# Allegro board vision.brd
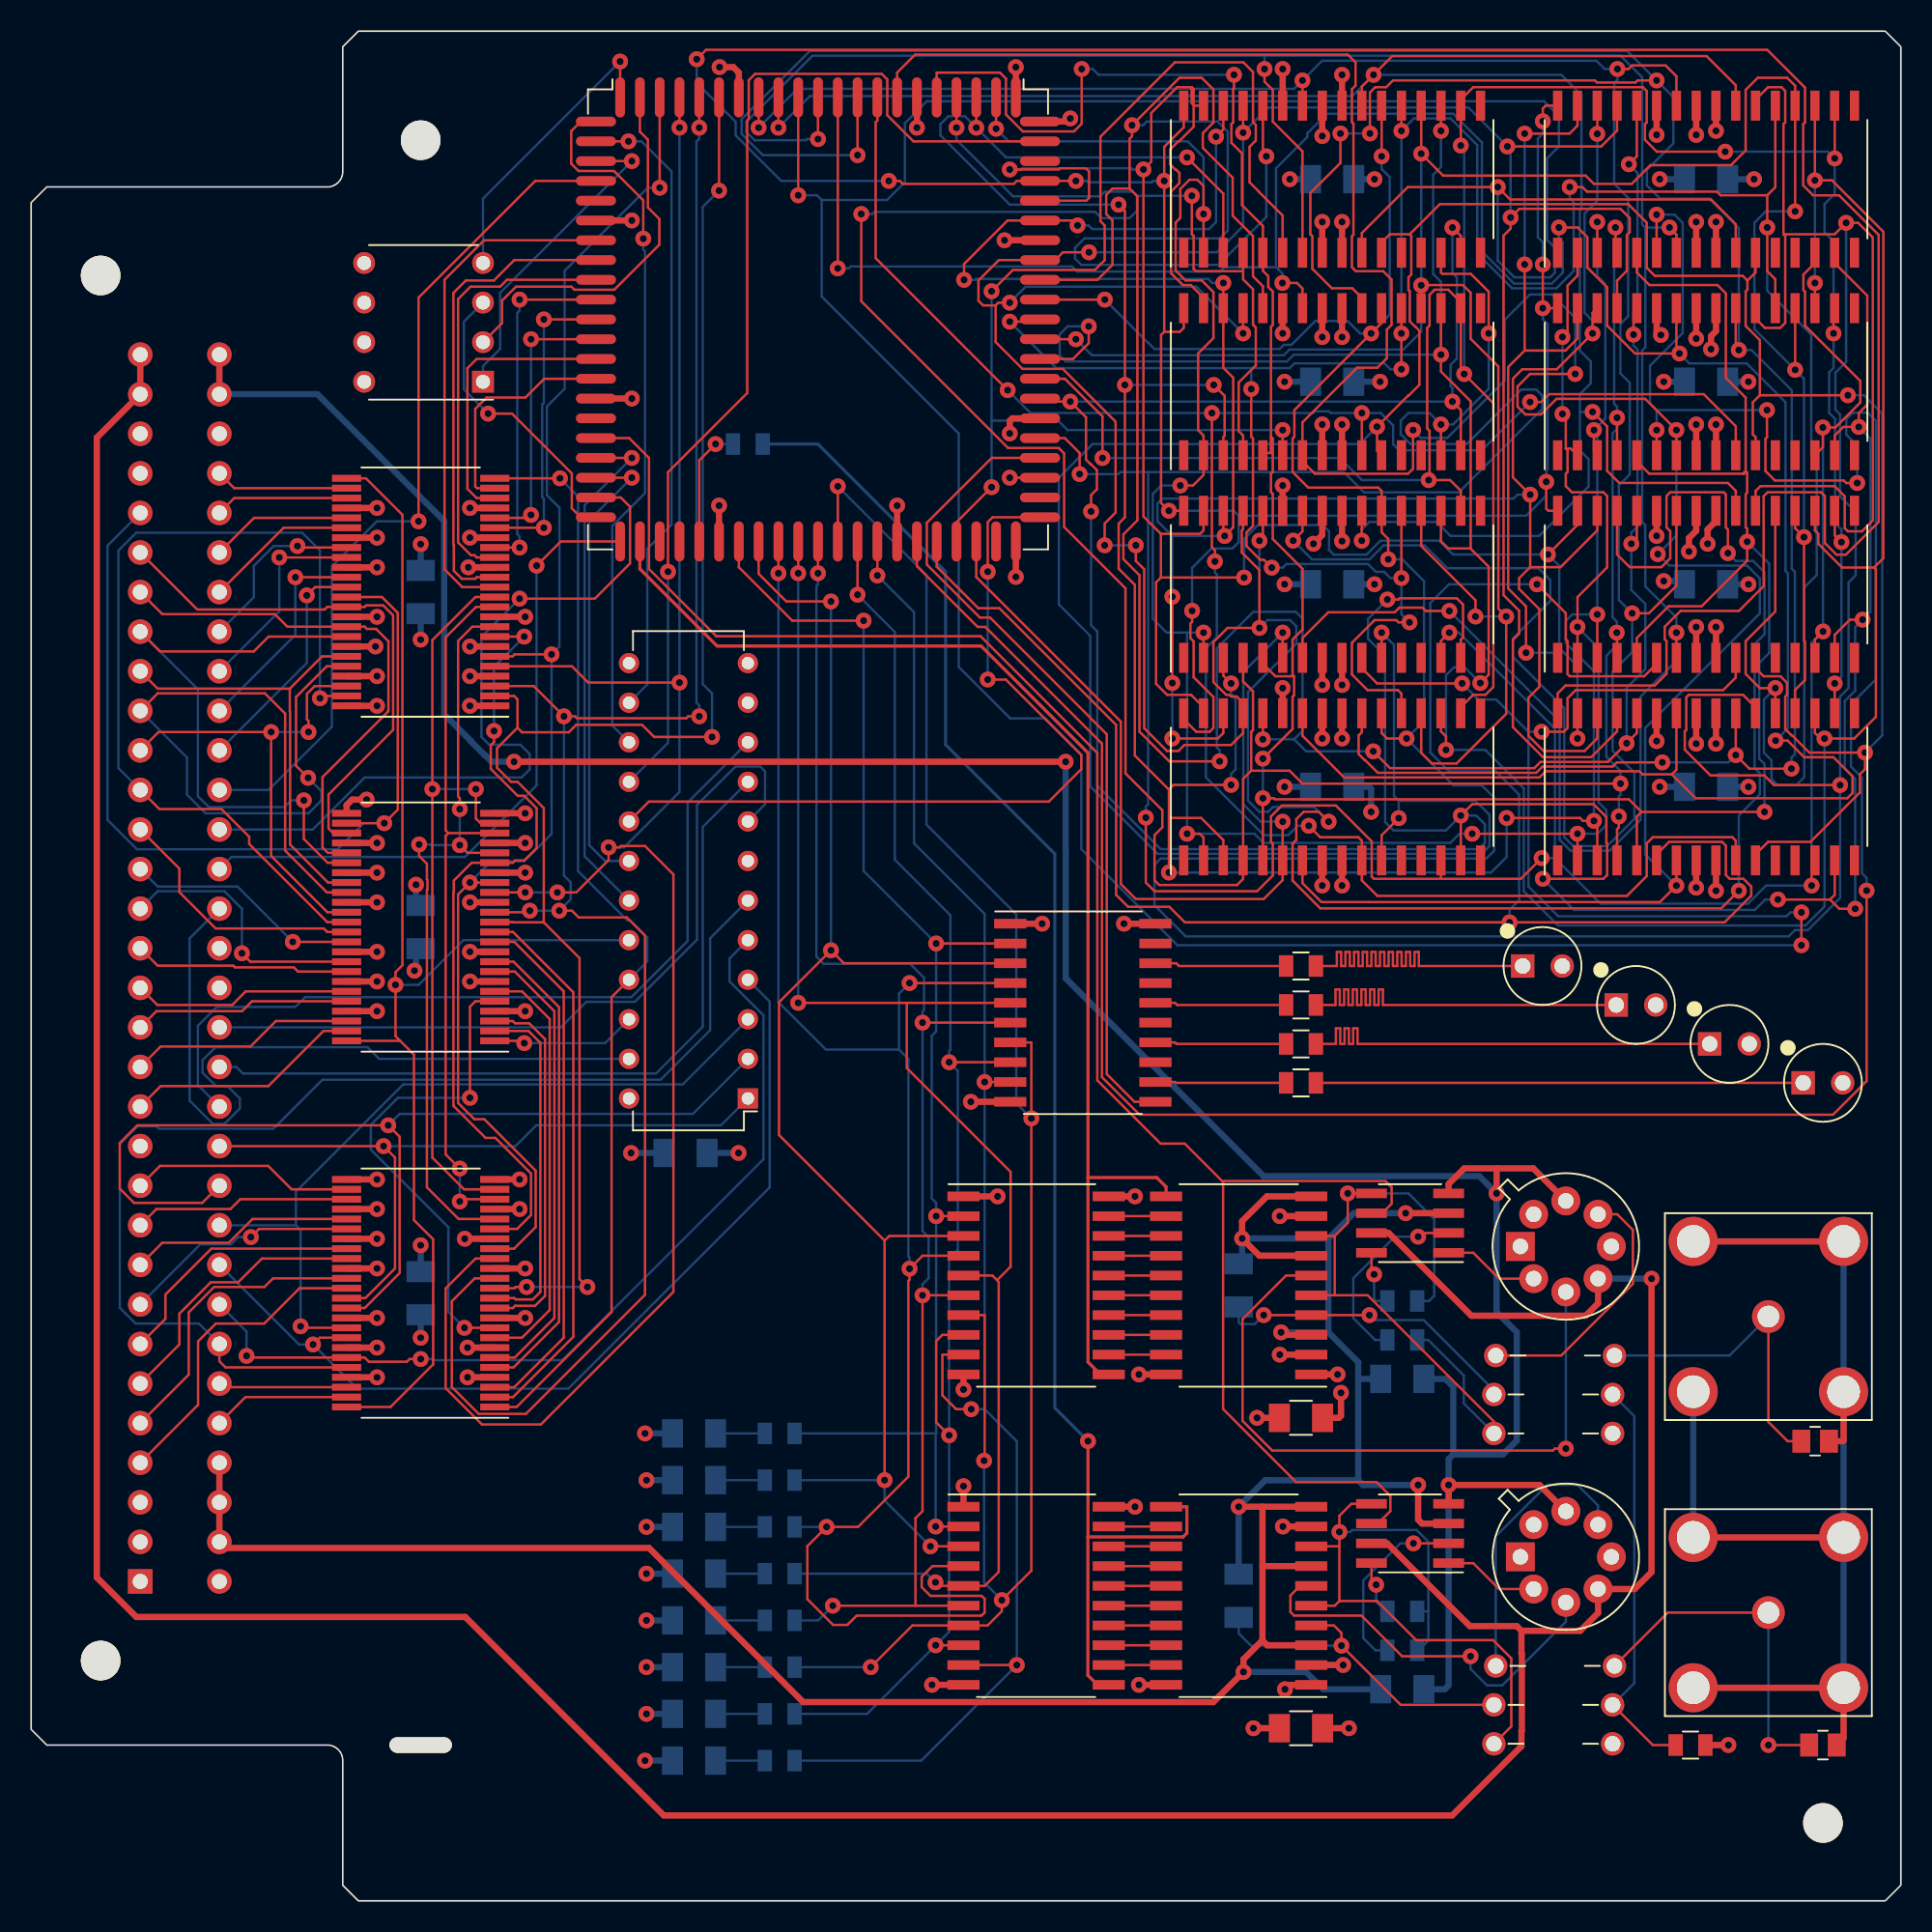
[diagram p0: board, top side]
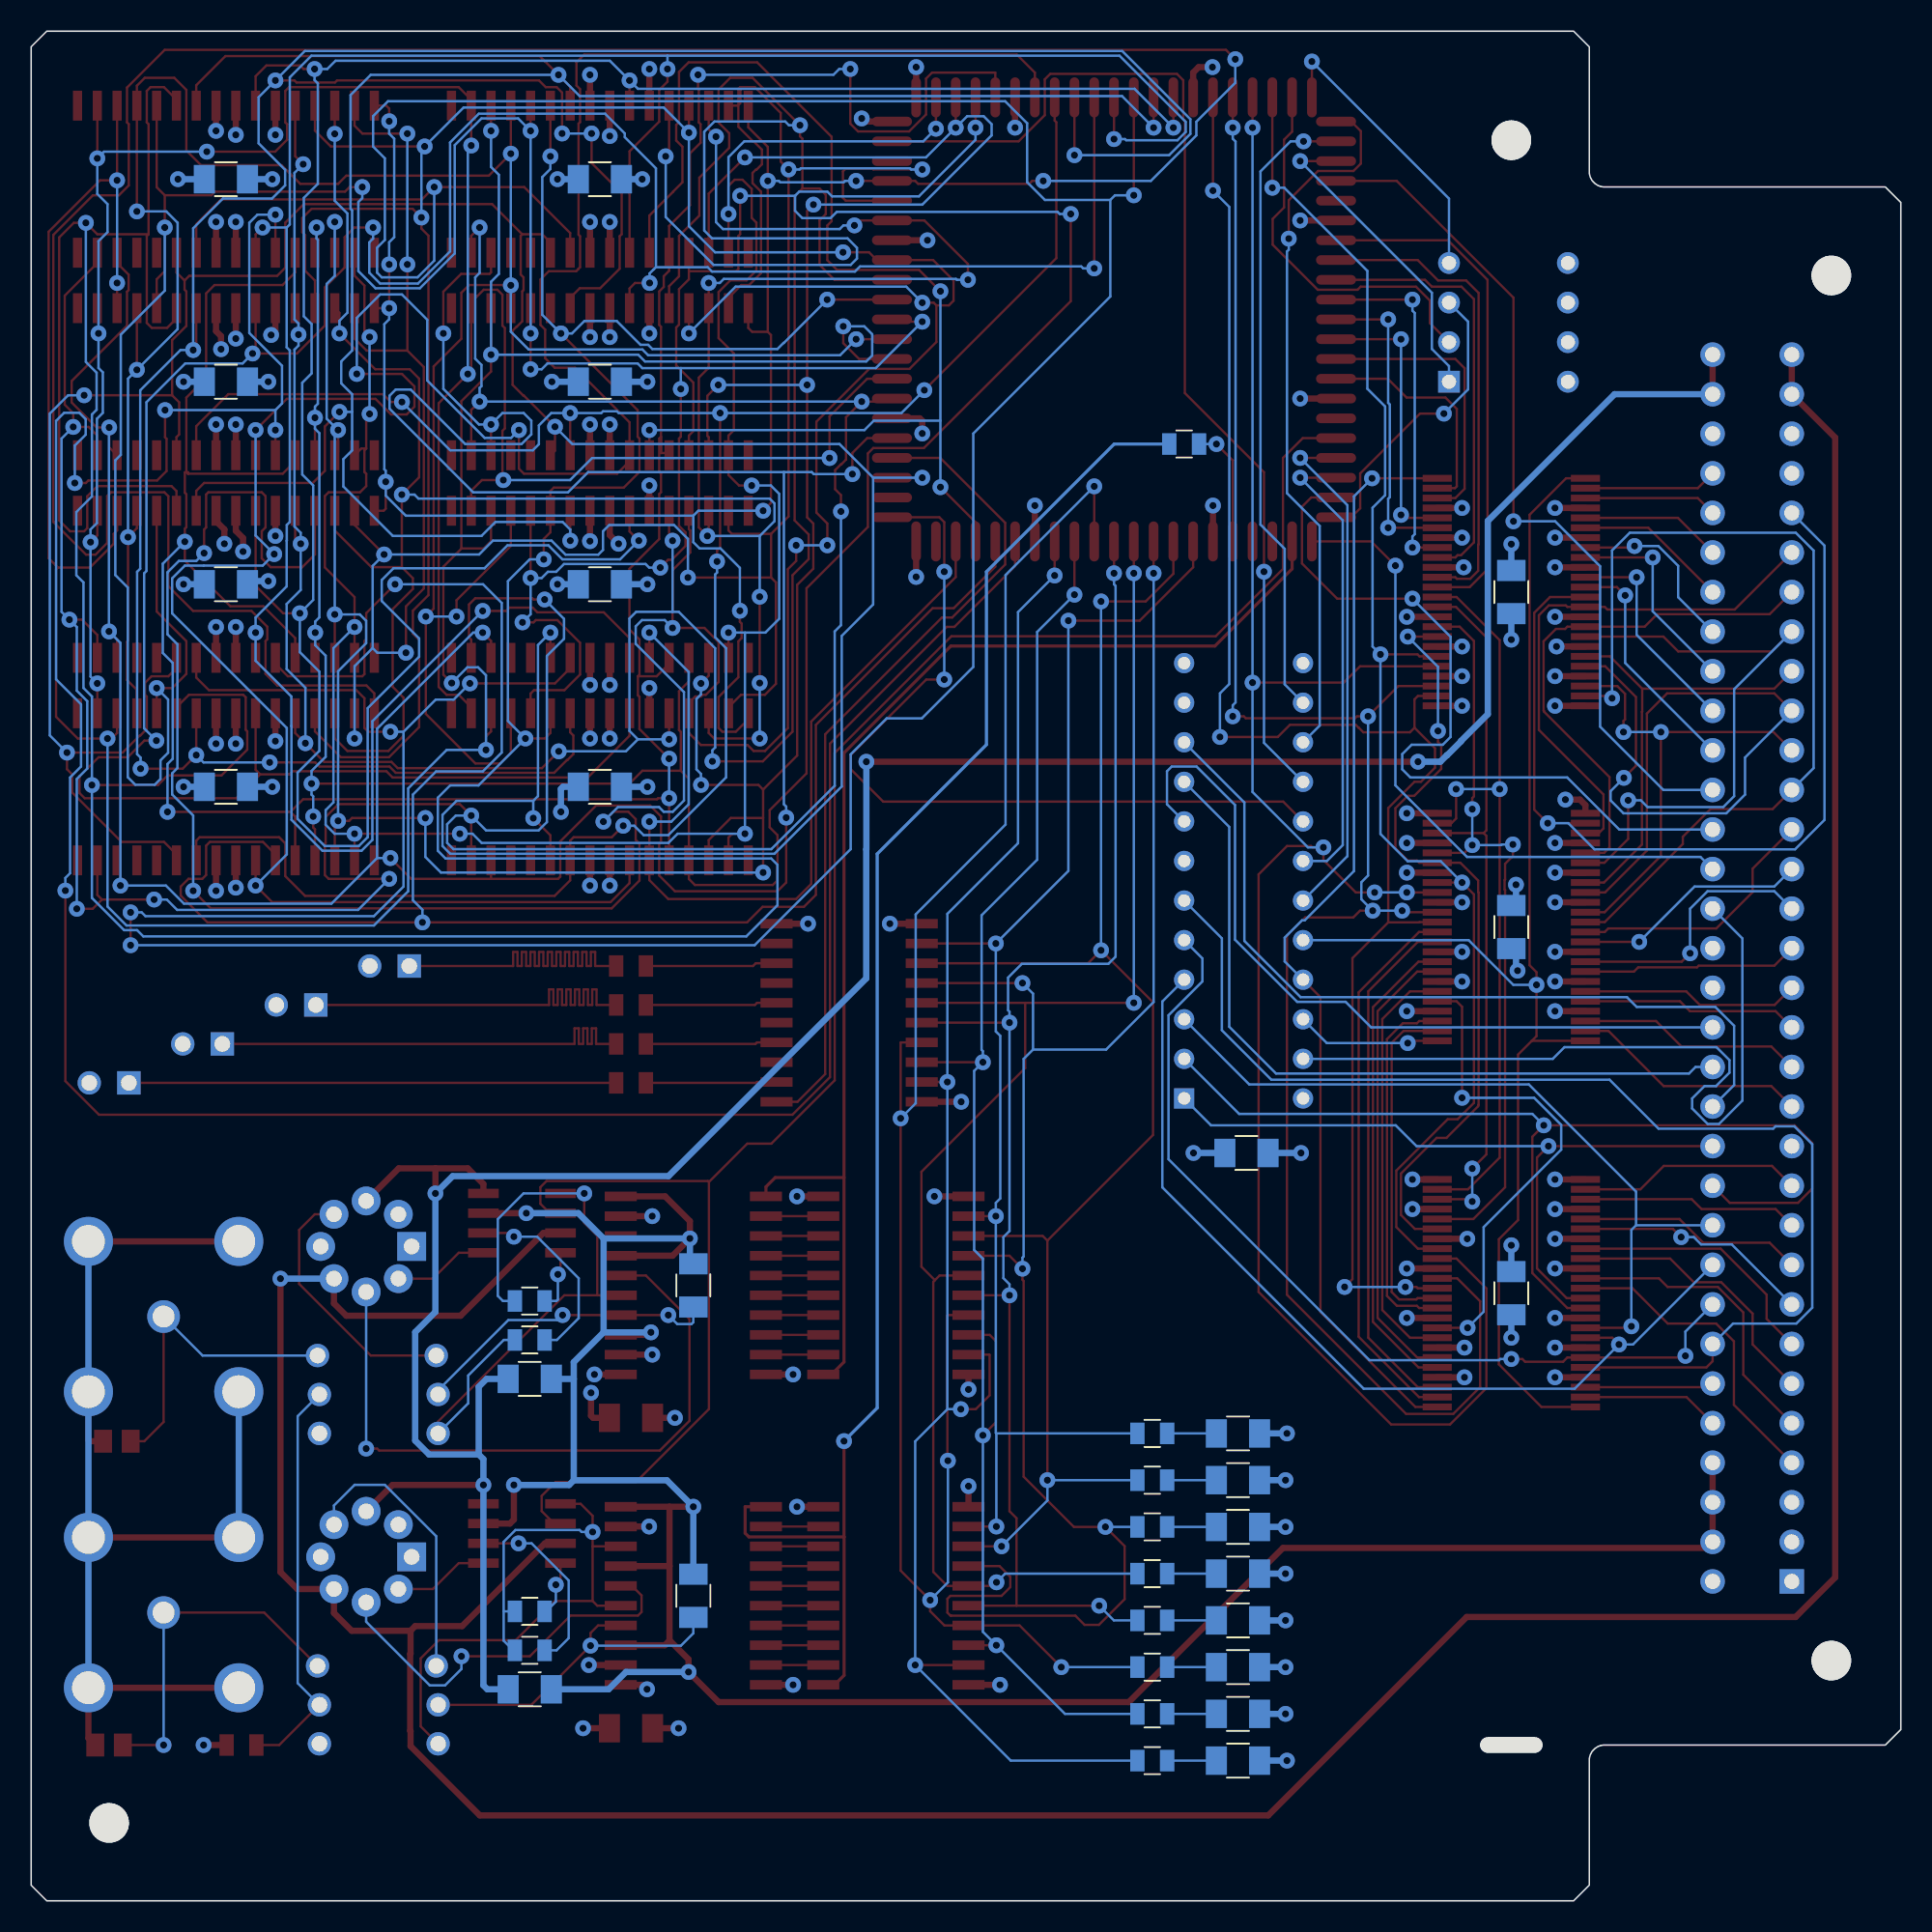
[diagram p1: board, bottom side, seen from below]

Outline 120 x 120 mm; copper layers: TOP, GND1, VCC1, VCC2, GND2, BOTTOM. Coordinates in mm from the lower left corner of the outline.

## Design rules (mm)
constraint set DEFAULT: min track width 0.15, pair gap 0.15
net group SYNC: nets VCLKA VCLKC
net group LEDNETS: nets LED1 LED2 LED3 LED4
net group MEMORY[0..28]: nets MEMORY.RA0 MEMORY.RA1 MEMORY.RA2 MEMORY.RA3 MEMORY.RA4 MEMORY.RA5 MEMORY.RA6 MEMORY.RA7 MEMORY.RA8 MEMORY.RA9 MEMORY.RA10 MEMORY.RA11 MEMORY.RA12 MEMORY.RA13 MEMORY.RA14 MEMORY.RA15 MEMORY.RCS0 MEMORY.RCS1 MEMORY.RCS2 MEMORY.RCS3 MEMORY.RD0 MEMORY.RD1 MEMORY.RD2 MEMORY.RD3 MEMORY.RD4 MEMORY.RD5 MEMORY.RD6 MEMORY.RD7 MEMORY.RWE
net group POWER: nets AGND GND_EARTH V12N V+12
net group VDNETS: nets VD0 VD1 VD2 VD3 VD4 VD5 VD6 VD7
nets with their own width: min track width 0.4; nets GND VCC

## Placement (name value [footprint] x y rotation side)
C1  0.1uF  [CAPC3216X110N]  25 39 90 bottom
C2  0.1uF  [CAPC3216X110N]  42 48 0 bottom
C3  0.1uF  [CAPC3216X110N]  25 62.5 90 bottom
C4  0.1uF  [CAPC3216X110N]  25 84 90 bottom
C5  47PF  [CAPC2012X110N]  114.5 29.5 0 top
C6  47PF  [CAPC2012X110N]  115 10 0 top
C7  0.01u  [CAPC3216X110N]  81.5 31 0 top
C8  0.01u  [CAPC3216X110N]  77.5 39.5 90 bottom
C9  0.1u  [CAPC3216X110N]  88 33.5 180 bottom
C10  0.01u  [CAPC3216X110N]  81.5 11.08 0 top
C11  0.01u  [CAPC3216X110N]  77.5 19.58 90 bottom
C12  0.1u  [CAPC3216X110N]  88 13.58 180 bottom
C13  330p  [CAPC3216X110N]  42.55 12 180 bottom
C14  330p  [CAPC3216X110N]  42.55 18 180 bottom
C15  330p  [CAPC3216X110N]  42.55 24 180 bottom
C16  330p  [CAPC3216X110N]  42.55 30 180 bottom
C17  330p  [CAPC3216X110N]  42.55 9 180 bottom
C18  330p  [CAPC3216X110N]  42.55 15 180 bottom
C19  330p  [CAPC3216X110N]  42.55 21 180 bottom
C20  330p  [CAPC3216X110N]  42.55 27 180 bottom
C21  0.1uF  [CAPC3216X110N]  83.5 71.5 0 bottom
C22  0.1uF  [CAPC3216X110N]  107.5 71.5 0 bottom
C23  0.1uF  [CAPC3216X110N]  83.5 84.5 0 bottom
C24  0.1uF  [CAPC3216X110N]  107.5 84.5 0 bottom
C25  0.1uF  [CAPC3216X110N]  83.5 97.5 0 bottom
C26  0.1uF  [CAPC3216X110N]  107.5 97.5 0 bottom
C27  0.1uF  [CAPC3216X110N]  107.5 110.5 0 bottom
C28  0.1uF  [CAPC3216X110N]  83.5 110.5 0 bottom
D1  LED  [LEDRD254W00D500H860P]  97 60 0 top
D2  LED  [LEDRD254W00D500H860P]  103 57.5 0 top
D3  LED  [LEDRD254W00D500H860P]  109 55 0 top
D4  LED  [LEDRD254W00D500H860P]  115 52.5 0 top
J1  CON64  [DIN64]  7 20.5 0 top
J2  BNC  [CONNEX_112659]  111.5 37.5 0 top
J3  BNC  [CONNEX_112659]  111.5 18.5 0 top
L1  47u  [INDAD762W79L381D254P]  94 35 0 top
L2  47u  [INDAD762W79L381D254P]  94 15.08 0 top
L3  47u  [INDAD762W79L381D254P]  101.5 32.5 180 top
L4  47u  [INDAD762W79L381D254P]  101.5 30 180 top
L5  47u  [INDAD762W79L381D254P]  101.5 12.58 180 top
L6  47u  [INDAD762W79L381D254P]  101.5 10.08 180 top
NOREF  -  []  20 6.38 0 top
NOREF#2  -  []  0 20.43 0 top
NOREF#3  -  []  -74.06 -89.06 0 top
NOREF#4  -  []  25 10 90 top
NOREF#5  -  []  115 5 90 top
NOREF#6  -  []  25 10 0 top
NOREF#7  -  [unnamed#2]  25 10 0 top
NOREF#8  -  []  25 10 90 top
NOREF#9  -  []  19.78 110.37 0 top
NOREF#10  -  []  25 10 0 top
NOREF#11  -  []  119.52 119.48 0 top
NOREF#12  -  []  25 10 90 top
NOREF#13  -  []  23 0 90 top
NOREF#14  -  []  192.64 154.78 0 top
R1  150  [RESC2012X60N]  81.5 60 0 top
R2  150  [RESC2012X60N]  81.5 57.5 0 top
R3  150  [RESC2012X60N]  81.5 55 0 top
R4  150  [RESC2012X60N]  81.5 52.5 0 top
R5  2K  [RESC2012X60N]  46 93.5 0 bottom
R6  100  [RESC2012X60N]  88 38.5 180 bottom
R7  100  [RESC2012X60N]  88 36 180 bottom
R8  100  [RESC2012X60N]  88 18.58 180 bottom
R9  100  [RESC2012X60N]  88 16.08 180 bottom
R10  10K  [RESC2012X60N]  48.05 12 0 bottom
R11  10K  [RESC2012X60N]  48.05 18 0 bottom
R12  10K  [RESC2012X60N]  48.05 24 0 bottom
R13  10K  [RESC2012X60N]  48.05 30 0 bottom
R14  10K  [RESC2012X60N]  48.05 9 0 bottom
R15  10K  [RESC2012X60N]  48.05 15 0 bottom
R16  10K  [RESC2012X60N]  48.05 21 0 bottom
R17  10K  [RESC2012X60N]  48.05 27 0 bottom
R18  10K  [RESC2012X60N]  106.5 10 0 top
U1  FCT16245  [SOP63P1035X279-48N]  25 39 90 top
U2  20L10  [DIP763W46P254L3204H508Q24P]  46 51.5 90 top
U3  FCT16245  [SOP63P1035X279-48N]  25 62.5 90 top
U4  FCT16245  [SOP63P1035X279-48N]  25 84 90 top
U5  EPF8282A_LCC  [PLCC127P3022X3022X457-84N]  50.5 101.5 270 top
U6  74ACT574  [SOIC127P1034X264-20N]  67.5 57 270 top
U7  EPC1064  [DIP763W46P254L991H419Q8P]  29 97.5 90 top
U8  TLC5602A  [SOIC127P1034X264-20N]  77.5 39.5 90 top
U9  TLE2037A  [TO292P469H584-8P]  98.5 42 0 top
U10  DG419AK  [SOIC127P600X175-8N]  88.5 43.5 90 top
U11  TLC5602A  [SOIC127P1034X264-20N]  77.5 19.58 90 top
U12  TLE2037A  [TO292P469H584-8P]  98.5 22.08 0 top
U13  DG419AK  [SOIC127P600X175-8N]  88.5 23.58 90 top
U14  74ACT574  [SOIC127P1034X264-20N]  64.5 39.5 270 top
U15  74ACT574  [SOIC127P1034X264-20N]  64.5 19.58 270 top
U16  TC55B4257  [SOIC127P1032X265-32N]  83.5 71.5 0 top
U17  TC55B4257  [SOIC127P1032X265-32N]  83.5 84.5 0 top
U18  TC55B4257  [SOIC127P1032X265-32N]  83.5 97.5 0 top
U19  TC55B4257  [SOIC127P1032X265-32N]  83.5 110.5 0 top
U20  TC55B4257  [SOIC127P1032X265-32N]  107.5 71.5 0 top
U21  TC55B4257  [SOIC127P1032X265-32N]  107.5 84.5 0 top
U22  TC55B4257  [SOIC127P1032X265-32N]  107.5 97.5 0 top
U23  TC55B4257  [SOIC127P1032X265-32N]  107.5 110.5 0 top

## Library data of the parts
C1-C4 C13-C20 = CAP NP
C5 C7-C9 = CAP NP: room: CHAN1
C6 C10-C12 = CAP NP: room: CHAN2
C21-C28 = CAP NP: room: MEM
D1-D4 = PHOTODIODE_0
J1 = CON64
J2 = BNC: room: CHAN1
J3 = BNC: room: CHAN2
L1 L3 L4 = INDUCTOR: room: CHAN1
L2 L5 L6 = INDUCTOR: room: CHAN2
R1-R4 = R: room: LED
R5 R10-R17 = R
R6 R7 = R: room: CHAN1
R8 R9 R18 = R: room: CHAN2
U1 U3 U4 = FCT16245
U2 = 20L10: alternate symbols: (T:SOIC24;B:SOIC24_PE)
U5 = EPF8282A/LCC
U6 = 74ACT574: room: LED
U7 = EPC1064
U8 = TLC5602A: room: CHAN1
U9 = TLE2037A: room: CHAN1
U10 = DG419AK: room: CHAN1
U11 = TLC5602A: room: CHAN2
U12 = TLE2037A: room: CHAN2
U13 = DG419AK: room: CHAN2
U14 = 74ACT574: room: CHAN1
U15 = 74ACT574: room: CHAN2
U16-U23 = TC55B4257: room: MEM

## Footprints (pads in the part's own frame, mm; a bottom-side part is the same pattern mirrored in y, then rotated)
CAPC2012X110N
  rect 1.15x1.47 smd: 1(-0.885,0) 2(0.885,0)
CAPC3216X110N
  rect 1.35x1.82 smd: 1(-1.385,0) 2(1.385,0)
CONNEX_112659
  round 2.1 hole 1.4: 1(0,0)
  round 3.15 hole 2.1: 2(-4.825,4.825) 3(4.825,4.825) 4(4.825,-4.825) 5(-4.825,-4.825)
DIN64
  round 2.54 hole 2.794 unplated: (-2.54,83.82) (-2.54,-5.08)
  rect 1.575x1.575 hole 0.965: 1(0,0)
  round 1.575 hole 0.965: 2(0,2.54) 3(0,5.08) 4(0,7.62) 5(0,10.16) 6(0,12.7) 7(0,15.24) 8(0,17.78) 9(0,20.32) 10(0,22.86) 11(0,25.4) 12(0,27.94) 13(0,30.48) 14(0,33.02) 15(0,35.56) 16(0,38.1) 17(0,40.64) 18(0,43.18) 19(0,45.72) 20(0,48.26) 21(0,50.8) 22(0,53.34) 23(0,55.88) 24(0,58.42) 25(0,60.96) 26(0,63.5) 27(0,66.04) 28(0,68.58) 29(0,71.12) 30(0,73.66) 31(0,76.2) 32(0,78.74) 33(5.08,0) 34(5.08,2.54) 35(5.08,5.08) 36(5.08,7.62) 37(5.08,10.16) 38(5.08,12.7) 39(5.08,15.24) 40(5.08,17.78) 41(5.08,20.32) 42(5.08,22.86) 43(5.08,25.4) 44(5.08,27.94) 45(5.08,30.48) 46(5.08,33.02) 47(5.08,35.56) 48(5.08,38.1) 49(5.08,40.64) 50(5.08,43.18) 51(5.08,45.72) 52(5.08,48.26) 53(5.08,50.8) 54(5.08,53.34) 55(5.08,55.88) 56(5.08,58.42) 57(5.08,60.96) 58(5.08,63.5) 59(5.08,66.04) 60(5.08,68.58) 61(5.08,71.12) 62(5.08,73.66) 63(5.08,76.2) 64(5.08,78.74)
DIP763W46P254L991H419Q8P
  rect 1.4x1.4 hole 0.9: 1(0,0)
  round 1.4 hole 0.9: 2(2.54,0) 3(5.08,0) 4(7.62,0) 5(7.62,7.63) 6(5.08,7.63) 7(2.54,7.63) 8(0,7.63)
DIP763W46P254L3204H508Q24P
  rect 1.3x1.3 hole 0.8: 1(0,0)
  round 1.3 hole 0.8: 2(2.54,0) 3(5.08,0) 4(7.62,0) 5(10.16,0) 6(12.7,0) 7(15.24,0) 8(17.78,0) 9(20.32,0) 10(22.86,0) 11(25.4,0) 12(27.94,0) 13(27.94,7.63) 14(25.4,7.63) 15(22.86,7.63) 16(20.32,7.63) 17(17.78,7.63) 18(15.24,7.63) 19(12.7,7.63) 20(10.16,7.63) 21(7.62,7.63) 22(5.08,7.63) 23(2.54,7.63) 24(0,7.63)
INDAD762W79L381D254P
  round 1.5 hole 1: 1(0,0) 2(7.62,0)
LEDRD254W00D500H860P
  round 1.5 hole 1: A(1.27,0)
  rect 1.5x1.5 hole 1: C(-1.27,0)
PLCC127P3022X3022X457-84N
  oval 2.57x0.62 smd: 1(-14.25,0) 2(-14.25,-1.27) 3(-14.25,-2.54) 4(-14.25,-3.81) 5(-14.25,-5.08) 6(-14.25,-6.35) 7(-14.25,-7.62) 8(-14.25,-8.89) 9(-14.25,-10.16) 10(-14.25,-11.43) 11(-14.25,-12.7) 33(14.25,-12.7) 34(14.25,-11.43) 35(14.25,-10.16) 36(14.25,-8.89) 37(14.25,-7.62) 38(14.25,-6.35) 39(14.25,-5.08) 40(14.25,-3.81) 41(14.25,-2.54) 42(14.25,-1.27) 43(14.25,0) 44(14.25,1.27) 45(14.25,2.54) 46(14.25,3.81) 47(14.25,5.08) 48(14.25,6.35) 49(14.25,7.62) 50(14.25,8.89) 51(14.25,10.16) 52(14.25,11.43) 53(14.25,12.7) 75(-14.25,12.7) 76(-14.25,11.43) 77(-14.25,10.16) 78(-14.25,8.89) 79(-14.25,7.62) 80(-14.25,6.35) 81(-14.25,5.08) 82(-14.25,3.81) 83(-14.25,2.54) 84(-14.25,1.27)
  oval 0.62x2.57 smd: 12(-12.7,-14.25) 13(-11.43,-14.25) 14(-10.16,-14.25) 15(-8.89,-14.25) 16(-7.62,-14.25) 17(-6.35,-14.25) 18(-5.08,-14.25) 19(-3.81,-14.25) 20(-2.54,-14.25) 21(-1.27,-14.25) 22(0,-14.25) 23(1.27,-14.25) 24(2.54,-14.25) 25(3.81,-14.25) 26(5.08,-14.25) 27(6.35,-14.25) 28(7.62,-14.25) 29(8.89,-14.25) 30(10.16,-14.25) 31(11.43,-14.25) 32(12.7,-14.25) 54(12.7,14.25) 55(11.43,14.25) 56(10.16,14.25) 57(8.89,14.25) 58(7.62,14.25) 59(6.35,14.25) 60(5.08,14.25) 61(3.81,14.25) 62(2.54,14.25) 63(1.27,14.25) 64(0,14.25) 65(-1.27,14.25) 66(-2.54,14.25) 67(-3.81,14.25) 68(-5.08,14.25) 69(-6.35,14.25) 70(-7.62,14.25) 71(-8.89,14.25) 72(-10.16,14.25) 73(-11.43,14.25) 74(-12.7,14.25)
RESC2012X60N
  rect 0.92x1.38 smd: 1(-0.955,0) 2(0.955,0)
SOIC127P600X175-8N
  rect 0.6x1.97 smd: 1(-1.905,-2.475) 2(-0.635,-2.475) 3(0.635,-2.475) 4(1.905,-2.475) 5(1.905,2.475) 6(0.635,2.475) 7(-0.635,2.475) 8(-1.905,2.475)
SOIC127P1032X265-32N
  rect 0.59x1.92 smd: 1(-9.525,-4.72) 2(-8.255,-4.72) 3(-6.985,-4.72) 4(-5.715,-4.72) 5(-4.445,-4.72) 6(-3.175,-4.72) 7(-1.905,-4.72) 8(-0.635,-4.72) 9(0.635,-4.72) 10(1.905,-4.72) 11(3.175,-4.72) 12(4.445,-4.72) 13(5.715,-4.72) 14(6.985,-4.72) 15(8.255,-4.72) 16(9.525,-4.72) 17(9.525,4.72) 18(8.255,4.72) 19(6.985,4.72) 20(5.715,4.72) 21(4.445,4.72) 22(3.175,4.72) 23(1.905,4.72) 24(0.635,4.72) 25(-0.635,4.72) 26(-1.905,4.72) 27(-3.175,4.72) 28(-4.445,4.72) 29(-5.715,4.72) 30(-6.985,4.72) 31(-8.255,4.72) 32(-9.525,4.72)
SOIC127P1034X264-20N
  rect 0.61x2.06 smd: 1(-5.715,-4.66) 2(-4.445,-4.66) 3(-3.175,-4.66) 4(-1.905,-4.66) 5(-0.635,-4.66) 6(0.635,-4.66) 7(1.905,-4.66) 8(3.175,-4.66) 9(4.445,-4.66) 10(5.715,-4.66) 11(5.715,4.66) 12(4.445,4.66) 13(3.175,4.66) 14(1.905,4.66) 15(0.635,4.66) 16(-0.635,4.66) 17(-1.905,4.66) 18(-3.175,4.66) 19(-4.445,4.66) 20(-5.715,4.66)
SOP63P1035X279-48N
  rect 0.44x1.87 smd: 1(-7.302,-4.755) 2(-6.668,-4.755) 3(-6.032,-4.755) 4(-5.398,-4.755) 5(-4.762,-4.755) 6(-4.128,-4.755) 7(-3.492,-4.755) 8(-2.858,-4.755) 9(-2.222,-4.755) 10(-1.588,-4.755) 11(-0.952,-4.755) 12(-0.318,-4.755) 13(0.318,-4.755) 14(0.952,-4.755) 15(1.588,-4.755) 16(2.222,-4.755) 17(2.858,-4.755) 18(3.492,-4.755) 19(4.128,-4.755) 20(4.762,-4.755) 21(5.398,-4.755) 22(6.032,-4.755) 23(6.668,-4.755) 24(7.302,-4.755) 25(7.302,4.755) 26(6.668,4.755) 27(6.032,4.755) 28(5.398,4.755) 29(4.762,4.755) 30(4.128,4.755) 31(3.492,4.755) 32(2.858,4.755) 33(2.222,4.755) 34(1.588,4.755) 35(0.952,4.755) 36(0.318,4.755) 37(-0.318,4.755) 38(-0.952,4.755) 39(-1.588,4.755) 40(-2.222,4.755) 41(-2.858,4.755) 42(-3.492,4.755) 43(-4.128,4.755) 44(-4.762,4.755) 45(-5.398,4.755) 46(-6.032,4.755) 47(-6.668,4.755) 48(-7.302,4.755)
TO292P469H584-8P
  rect 1.85x1.85 hole 1: 1(-2.921,0)
  round 1.85 hole 1: 2(-2.066,-2.066) 3(0,-2.921) 4(2.066,-2.066) 5(2.921,0) 6(2.066,2.066) 7(0,2.921) 8(-2.066,2.066)
unnamed#2
  round 2.54 hole 2.794 unplated: (0,103) (90,-5)
  oval 4x1 hole 5x1.5 unplated: (0,0)

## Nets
AGND: C8.2 C9.2 C11.2 C12.2 J1.34 J1.35 J1.36 U8.3 U8.7 U8.10 U10.3 U11.3 U11.7 U11.10 U13.3
GND: C1.2 C2.2 C3.2 C4.2 C7.2 C10.2 C13.2 C14.2 C15.2 C16.2 C17.2 C18.2 C19.2 C20.2 C21.2 C22.2 C23.2 C24.2 C25.2 C26.2 C27.2 C28.2 J1.1 J1.2 J1.3 J1.33 R18.2 U1.4 U1.10 U1.15 U1.21 U1.24 U1.25(G\) U1.28 U1.34 U1.39 U1.45 U2.11 U2.12 U2.13 U3.4 U3.10 U3.15 U3.21 U3.24 U3.25(G\) U3.28 U3.34 U3.39 U3.45 U4.1 U4.4 U4.10 U4.15 U4.21 U4.28 U4.34 U4.39 U4.45 U4.48 U5.5 U5.26 U5.47 U5.53 U5.68 U5.74 U5.75 U6.1 U6.10 U7.5 U8.1 U8.20 U11.1 U11.20 U14.1 U14.10 U15.1 U15.10 U16.9 U16.25 U16.27 U17.9 U17.25 U17.27 U18.9 U18.25 U18.27 U19.9 U19.25 U19.27 U20.9 U20.25 U20.27 U21.9 U21.25 U21.27 U22.9 U22.25 U22.27 U23.9 U23.25 U23.27
GND_EARTH: C5.2 C6.2 J2.2 J2.3 J2.4 J2.5(GND5) J3.2 J3.3 J3.4 J3.5(GND5)
V12N: J1.31 J1.32 U9.4(V-) U10.7 U12.4(V-) U13.7
VCC: C1.1 C2.1 C3.1 C4.1 C7.1 C10.1 C21.1 C22.1 C23.1 C24.1 C25.1 C26.1 C27.1 C28.1 D1.A D2.A D3.A D4.A J1.29 J1.30 J1.62 L4.1 L6.1 U1.7 U1.18 U1.31 U1.42 U2.24(VCC) U3.7 U3.18 U3.31 U3.42 U4.7 U4.18 U4.31 U4.42 U5.17 U5.38 U5.59 U5.80 U6.20 U7.7 U7.8 U8.2 U8.9(VD2) U11.2 U11.9(VD2) U14.20 U15.20 U16.8 U16.24 U17.8 U17.24 U18.8 U18.24 U19.8 U19.24 U20.8 U20.24 U21.8 U21.24 U22.8 U22.24 U23.8 U23.24
A0: J1.54 U4.36
A1: J1.55 U4.35
A2: J1.56 U4.33
A3: J1.57 U4.32
A4: J1.58 U4.30
A5: J1.59 U4.29
A6: J1.60 U4.27
A7: J1.61 U4.26
A8: J1.13 U3.47
A9: J1.14 U3.46
A10: J1.15 U3.44
A11: J1.16 U3.43
A12: J1.17 U3.41
A13: J1.18 U3.40
A14: J1.19 U3.38
A15: J1.20 U3.37
A16: J1.37 U1.47
A17: J1.38 U1.46
A18: J1.39 U1.44 U2.6
A19: J1.40 U1.43 U2.5
A20: J1.41 U1.41 U2.4
A21: J1.42 U1.40 U2.3
A22: J1.43 U1.38 U2.2
A23: J1.44 U1.37 U2.1
AEN: J1.47 U2.8
BA0: U1.13 U3.13 U4.2 U5.6
BA1: U1.14 U3.14 U4.3 U5.7
BA2: U1.16 U3.16 U4.5 U5.8
BA3: U1.17 U3.17 U4.6 U5.9
BA4: U1.19 U3.19 U4.8
BA5: U1.20 U3.20 U4.9
BA6: U1.22 U3.22 U4.11
BA7: U1.23 U3.23 U4.12
BD0: U4.23 U5.25
BD1: U4.22 U5.24
BD2: U4.20 U5.23
BD3: U4.19 U5.22
BD4: U4.17 U5.21
BD5: U4.16 U5.20
BD6: U4.14 U5.19
BD7: U4.13 U5.18
BD8: U1.12 U3.2
BD9: U1.11 U3.3
BD10: U1.9 U3.5
BD11: U1.8 U3.6
BD12: U1.6 U3.8
BD13: U1.5 U3.9
BD14: U1.3 U3.11
BD15: U1.2 U3.12
BNC2: C5.1 J2.1 L1.2
BNC3: C6.1 J3.1 L2.2
BRD: U2.16 U5.73
BRESET: U2.15 U5.12
BWR: U2.17 U5.54
D0: J1.28 U3.26 U4.37
D1: J1.27 U3.27 U4.38
D2: J1.26 U3.29 U4.40
D3: J1.25 U3.30 U4.41
D4: J1.24 U3.32 U4.43
D5: J1.23 U3.33 U4.44
D6: J1.22 U3.35 U4.46
D7: J1.21 U3.36 U4.47
D8: J1.4 U1.36
D9: J1.5 U1.35
D10: J1.6 U1.33
D11: J1.7 U1.32
D12: J1.8 U1.30
D13: J1.9 U1.29
D14: J1.10 U1.27
D15: J1.11 U1.26
DATA: U5.14 U7.1
DCLK: U5.10 U7.2
DDIR: U1.48 U2.20 U3.48 U4.25(G\)
DEN: U1.1 U2.21 U4.24
DHEN: U2.22 U3.1
FPGA: U2.18 U5.30
GAIN: U5.28 U10.6 U13.6
HS: U2.19 U5.29
LED1: D1.C(CATHODE) R1.2
LED2: D2.C(CATHODE) R2.2
LED3: D3.C(CATHODE) R3.2
LED4: D4.C(CATHODE) R4.2
MCLK: J1.52 U5.31
MEMORY.RA0: U5.79 U16.5 U17.5 U18.5 U19.5 U20.5 U21.5 U22.5 U23.5
MEMORY.RA1: U5.78 U16.4 U17.4 U18.4 U19.4 U20.4 U21.4 U22.4 U23.4
MEMORY.RA2: U5.77 U16.3 U17.3 U18.3 U19.3 U20.3 U21.3 U22.3 U23.3
MEMORY.RA3: U5.76 U16.2 U17.2 U18.2 U19.2 U20.2 U21.2 U22.2 U23.2
MEMORY.RA4: U5.71 U16.32 U17.32 U18.32 U19.32 U20.32 U21.32 U22.32 U23.32
MEMORY.RA5: U5.70 U16.31 U17.31 U18.31 U19.31 U20.31 U21.31 U22.31 U23.31
MEMORY.RA6: U5.69 U16.30 U17.30 U18.30 U19.30 U20.30 U21.30 U22.30 U23.30
MEMORY.RA7: U5.67 U16.29 U17.29 U18.29 U19.29 U20.29 U21.29 U22.29 U23.29
MEMORY.RA8: U5.66 U16.28 U17.28 U18.28 U19.28 U20.28 U21.28 U22.28 U23.28
MEMORY.RA9: U5.65 U16.22 U17.22 U18.22 U19.22 U20.22 U21.22 U22.22 U23.22
MEMORY.RA10: U5.64 U16.21 U17.21 U18.21 U19.21 U20.21 U21.21 U22.21 U23.21
MEMORY.RA11: U5.63 U16.20 U17.20 U18.20 U19.20 U20.20 U21.20 U22.20 U23.20
MEMORY.RA12: U5.62 U16.19 U17.19 U18.19 U19.19 U20.19 U21.19 U22.19 U23.19
MEMORY.RA13: U5.61 U16.18 U17.18 U18.18 U19.18 U20.18 U21.18 U22.18 U23.18
MEMORY.RA14: U5.60 U16.15 U17.15 U18.15 U19.15 U20.15 U21.15 U22.15 U23.15
MEMORY.RA15: U5.58 U16.14 U17.14 U18.14 U19.14 U20.14 U21.14 U22.14 U23.14
MEMORY.RCS0: U5.51 U16.6 U17.6
MEMORY.RCS1: U5.50 U18.6 U19.6
MEMORY.RCS2: U5.49 U20.6 U21.6
MEMORY.RCS3: U5.48 U22.6 U23.6
MEMORY.RD0: U5.81 U16.7 U18.7 U20.7 U22.7
MEMORY.RD1: U5.82 U16.10 U18.10 U20.10 U22.10
MEMORY.RD2: U5.83 U16.23 U18.23 U20.23 U22.23
MEMORY.RD3: U5.84 U16.26 U18.26 U20.26 U22.26
MEMORY.RD4: U5.1 U17.7 U19.7 U21.7 U23.7
MEMORY.RD5: U5.2 U17.10 U19.10 U21.10 U23.10
MEMORY.RD6: U5.3 U17.23 U19.23 U21.23 U23.23
MEMORY.RD7: U5.4 U17.26 U19.26 U21.26 U23.26
MEMORY.RWE: U5.56 U16.11(W\E\) U17.11(W\E\) U18.11(W\E\) U19.11(W\E\) U20.11(W\E\) U21.11(W\E\) U22.11(W\E\) U23.11(W\E\)
MRD: J1.46 U2.9
MWR: J1.45 U2.10
N00036_DATA_DAAMP: L4.2 R6.1 R7.1 U8.5 U8.8 U10.5(VL)
N00036_DATA_DAAMP1: L6.2 R8.1 R9.1 U11.5 U11.8 U13.5(VL)
N00038_DATA_DAAMP: C8.1 L3.2 U8.4
N00038_DATA_DAAMP1: C11.1 L5.2 U11.4
N00044_DATA_DAAMP: U9.2 U10.1
N00044_DATA_DAAMP1: U12.2 U13.1
N00060_DATA_DAAMP: U8.6 U9.3
N00060_DATA_DAAMP1: U11.6 U12.3
N282866_DATA_DAAMP: R6.2 U10.8
N282866_DATA_DAAMP1: R8.2 U13.8
N282912_DATA_DAAMP: R7.2 U10.2
N282912_DATA_DAAMP1: R9.2 U13.2
NCS: U5.11 U7.4
OE: U5.32 U7.3(OE)
OUTA: L1.1 U9.6
OUTB: L2.1 U12.6
Q0: R1.1 U6.18
Q1: R2.1 U6.16
Q2: R3.1 U6.14
Q3: R4.1 U6.12(Q8)
RDY: J1.50 U2.23
RESET: J1.53 U5.15
SEL: U2.14 U5.13
V+12: C9.1 C12.1 J1.63 J1.64 U9.7 U10.4 U12.7 U13.4
VCLKA: U5.34 U8.11 U14.11
VCLKC: R5.2 U11.11 U15.11
VD0: R13.2 U5.39 U6.2 U14.2 U15.2
VD1: R17.2 U5.40 U6.3 U14.3 U15.3
VD2: R12.2 U5.41 U6.4 U14.4 U15.4
VD3: R16.2 U5.42 U6.5 U14.5 U15.5
VD4: R11.2 U5.43 U6.6 U14.6 U15.6
VD5: R15.2 U5.44 U6.7 U14.7 U15.7
VD6: R10.2 U5.45 U6.8 U14.8 U15.8
VD7: R14.2 U5.46(VD7) U6.9 U14.9 U15.9
VREF: L3.1 L5.1 R18.1
WAIT: J1.51 U5.33
WSTAT: U5.57 U6.11
N14843: C19.1 R16.1
N14849: C15.1 R12.1
N14853: C20.1 R17.1
N14855: C16.1 R13.1
N15143: C17.1 R14.1
N15151: C13.1 R10.1
N15155: C18.1 R15.1
N15161: C14.1 R11.1
N58063: U8.12 U14.19
N58118: U8.13 U14.18
N58173: U8.14 U14.17
N58228: U8.15 U14.16
N58283: U8.16 U14.15
N58338: U8.17 U14.14
N58393: U8.18 U14.13
N58448: U8.19 U14.12(Q8)
N58834: U11.12 U15.19
N58889: U11.13 U15.18
N58944: U11.14 U15.17
N58999: U11.15 U15.16
N59054: U11.16 U15.15
N59109: U11.17 U15.14
N59164: U11.18 U15.13
N59219: U11.19 U15.12(Q8)
N409523: R5.1 U5.37

Pads without a net: J1 12 48 49; U2 7; U5 16 27 35 36 52 55 72; U6 13 15 17 19; U7 6; U9 1 5 8; U12 1 5 8; U16 1 12 13 16 17; U17 1 12 13 16 17; U18 1 12 13 16 17; U19 1 12 13 16 17; U20 1 12 13 16 17; U21 1 12 13 16 17; U22 1 12 13 16 17; U23 1 12 13 16 17

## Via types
v1: diameter 1.016, hole 0.457, TOP to BOTTOM, 486 vias

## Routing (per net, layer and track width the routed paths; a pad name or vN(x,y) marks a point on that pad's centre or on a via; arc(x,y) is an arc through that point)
AGND: length 177.8
  TOP w0.4: U8.3 80.38,36.33 v1(80.22,36.49) ; v1(77.5,25.29) 79.03,25.29 ; 79.03,25.29 U11.10 ; 79.03,25.29 79.03,21.48 ; J1.36 J1.35 J1.34 12.47,22.65 39.65,22.65 49.55,12.76 75.88,12.76 v1(77.81,14.69) 77.81,15.5 79.01,16.7 79.03,16.7 ; 79.03,16.7 79.03,21.48 ; 79.03,16.7 79.33,16.4 U11.3 ; 79.03,21.48 U11.7 ; v1(89.02,26.69) 89.02,24.47 89.27,24.21 U13.3 ; U8.10 79.31,45.22 77.72,43.63 v1(77.72,42.51) 78.83,41.41 U8.7 ; U10.3 v1(88.22,44.13)
  BOTTOM w0.4: C12.2 82.93,13.58 81.83,14.69 v1(77.81,14.69) ; 85.17,26.99 85.47,26.69 v1(89.02,26.69) ; 85.17,26.99 85.17,33.5 ; 85.17,26.99 79.2,26.99 v1(77.5,25.29) C11.2 ; 85.17,33.5 C9.2 ; 85.17,33.5 85.17,34.57 83.26,36.49 ; v1(80.22,36.49) 83.26,36.49 ; 83.26,36.49 83.26,42.51 ; 83.26,42.51 v1(77.72,42.51) 77.72,41.11 C8.2 ; 83.26,42.51 84.88,44.13 v1(88.22,44.13)
GND: length 232.5
  TOP w0.4: U19.27 v1(80.33,117.57) ; U5.47 v1(55.58,89.55) ; U4.39 v1(22.2,82.41) ; U3.28 v1(22.2,67.9) ; U5.75 v1(63.2,117.69) ; U16.25 v1(82.87,74.6) ; U18.27 v1(80.33,100.6) ; U19.9 v1(84.13,107.76) ; U4.28 v1(22.2,89.4) ; v1(44.18,117.69) 45.07,117.69 45.42,117.34 U5.5 ; U15.1 v1(59.84,26.62) ; U17.27 v1(80.33,90.84) ; U1.21 v1(31.35,44.4) ; U20.25 v1(106.86,74.27) ; U1.45 v1(22.2,33.6) ; U22.9 v1(108.14,94.76) ; U6.1 v1(64.89,62.72) ; 20.25,46.3 v1(22.2,46.3) ; v1(84.07,32.61) 84.07,31.14 83.93,31 C7.2 ; U22.27 104.33,100.78 v1(104.6,100.5) ; U3.15 v1(28.16,64.09) ; U3.39 v1(22.2,60.91) ; U3.4 v1(31.71,57.1) ; U23.25 v1(106.86,113.34) ; U15.10 v1(57.82,13.86) ; U5.74 66.5,114.2 v1(66.69,114.4) ; v1(80.47,13.58) 80.76,13.86 U11.1 ; U4.48 v1(22.2,76.7) ; U3.10 v1(28.16,60.91) ; U3.34 v1(22.2,64.09) ; R18.2 v1(108.93,10) ; U21.9 v1(108.14,81.76) ; U5.26 v1(38.55,96.42) ; U4.15 v1(28.06,85.59) ; U4.10 v1(31.71,82.41) ; U14.10 v1(59.84,32.82) ; C10.2 v1(84.58,11.08) ; U4.45 v1(22.2,78.6) ; U16.9 v1(84.13,65.16) ; U4.21 v1(28.16,89.4) ; U21.25 106.86,87.93 106.4,87.47 v1(106.4,86.6) ; U1.24 v1(31.35,46.3) ; U18.9 v1(84.13,94.76) ; U3.21 v1(31.71,67.9) ; U1.15 v1(31.71,40.59) ; 20.25,69.8 20.25,70.33 20.6,70.68 v1(21.53,70.68) ; U18.25 v1(82.87,100.37) ; U23.27 v1(104.33,113.34) ; U1.4 v1(28.01,33.6) ; U8.20 v1(71.1,33.78) ; U17.9 v1(84.13,78.04) ; U5.68 v1(62.47,106.58) ; U3.45 v1(22.2,57.1) ; U1.34 v1(22.2,40.59) ; U3.24 v1(31.71,69.8) ; U4.34 v1(22.2,85.59) ; U17.25 82.87,87.67 v1(82.3,87.1) ; U6.10 v1(60.31,51.28) ; 29.75,76.7 v1(28.16,76.7) ; U22.25 v1(106.86,100.27) ; U1.10 v1(31.71,37.41) ; U21.27 v1(104.33,87.6) ; U1.39 v1(22.2,37.41) ; U1.28 v1(22.2,44.4) ; U11.20 v1(71.1,13.86) ; U20.27 v1(104.33,74.43) ; U5.53 v1(63.2,84.97) ; U4.4 v1(28.16,78.6) ; U20.9 v1(108.14,64.83) ; U16.27 v1(80.33,77.84) ; U19.25 v1(82.87,113.27) ; U23.9 v1(108.14,107.76) ; U8.1 v1(83.85,33.78) ; U14.1 v1(62.03,45.22)
  GND1 w0.4: J1.1 7,21.47 ; J1.1 7,19.53 ; J1.1 7.97,20.5 ; J1.1 6.03,20.5 ; 45.17,76.9 U2.11 ; U2.11 46.83,76.9 ; U2.11 46,77.73 ; U2.11 46,76.07 ; J1.3 7,26.55 ; J1.3 6.03,25.58 ; J1.3 7.97,25.58 ; J1.3 7,24.61 ; J1.33 13.05,20.5 ; J1.33 12.08,21.47 ; J1.33 12.08,19.53 ; J1.33 11.11,20.5 ; 20.49,105.12 U7.5 ; U7.5 21.37,106 ; U7.5 21.37,104.24 ; U7.5 22.25,105.12 ; U2.13 39.2,79.44 ; U2.13 38.37,78.61 ; U2.13 37.54,79.44 ; U2.13 38.37,80.27 ; J1.2 7.97,23.04 ; J1.2 7,24.01 ; J1.2 7,22.07 ; J1.2 6.03,23.04 ; 46,78.61 U2.12 ; U2.12 46,80.27 ; U2.12 45.17,79.44 ; U2.12 46.83,79.44
  GND2 w0.4: U7.5 21.37,106 ; U7.5 22.25,105.12 ; U7.5 20.49,105.12 ; U7.5 21.37,104.24 ; U2.12 46.83,79.44 ; U2.12 46,78.61 ; U2.12 46,80.27 ; U2.12 45.17,79.44 ; J1.33 13.05,20.5 ; J1.33 11.11,20.5 ; J1.33 12.08,19.53 ; J1.33 12.08,21.47 ; 37.54,79.44 U2.13 ; U2.13 39.2,79.44 ; U2.13 38.37,80.27 ; U2.13 38.37,78.61 ; J1.3 7,26.55 ; J1.3 7,24.61 ; J1.3 6.03,25.58 ; J1.3 7.97,25.58 ; 46,76.07 U2.11 ; U2.11 46,77.73 ; U2.11 46.83,76.9 ; U2.11 45.17,76.9 ; J1.2 7,24.01 ; J1.2 6.03,23.04 ; J1.2 7.97,23.04 ; J1.2 7,22.07 ; 6.03,20.5 J1.1 ; J1.1 7,19.53 ; J1.1 7.97,20.5 ; J1.1 7,21.47
  BOTTOM w0.4: C4.2 v1(25,87.08) ; C17.2 v1(39.4,9) ; C1.2 v1(25,42.08) ; C15.2 v1(39.49,24) ; C26.2 v1(110.22,97.5) ; C28.2 v1(86.22,110.5) ; C25.2 v1(86.58,97.5) ; v1(24.7,65.22) 24.7,64.18 C3.2 ; C16.2 v1(39.4,30) ; v1(86,69.89) 86,71.37 85.87,71.5 C21.2 ; C19.2 v1(39.49,21) ; C24.2 v1(110.22,84.5) ; C22.2 v1(110.22,71.5) ; C27.2 v1(110.58,110.5) ; C13.2 v1(39.49,12) ; C20.2 v1(39.49,27) ; C2.2 v1(45.4,48) ; C14.2 v1(39.49,18) ; C23.2 v1(86.22,84.5) ; C18.2 v1(39.49,15)
GND_EARTH: length 74.9
  TOP w0.4: C6.2 116.33,10.44 J3.4 J3.5 ; J2.2 J2.3 ; J2.4 116.33,29.56 116.27,29.5 C5.2 ; J3.3 J3.2
  BOTTOM w0.4: J2.5 J3.2 ; J2.3 J2.4 J3.3 J3.4
V12N: length 250.4
  TOP w0.4: v1(104,39.93) 104,21.1 102.91,20.01 100.57,20.01 100.57,18.48 99.42,17.33 95.65,17.33 ; 95.65,17.33 95.35,17.63 92.34,17.63 87.03,22.94 U13.7 ; 95.65,17.33 95.65,15.87 95.67,15.84 95.67,10.92 95.65,10.89 95.65,9.93 91.2,5.48 40.6,5.48 27.87,18.22 6.75,18.22 4.21,20.76 4.21,93.91 J1.31 J1.32 ; U9.4 100.57,38.35 99.77,37.55 92.44,37.55 87.12,42.87 U10.7
  BOTTOM w0.4: v1(104,39.93) U9.4
VCC: length 186.6
  TOP w0.4: U8.9 v1(80.14,43.95) ; U14.20 v1(70.85,45.22) ; U4.18 v1(28.16,87.49) ; U21.24 108.14,88.56 107.61,88.03 107.61,88.01 107.6,88 v1(107.6,87.1) ; U4.31 v1(22.2,87.49) ; U3.31 v1(22.2,65.99) ; U17.8 v1(82.87,78.04) ; U3.18 v1(31.71,65.99) ; U8.2 v1(80.14,35.05) ; U1.42 v1(22.2,35.51) ; U4.7 v1(28.16,80.51) ; U16.24 v1(84.13,74.6) ; C7.1 v1(78.68,31) ; U1.18 v1(27.83,42.49) ; U16.8 v1(82.87,65.16) ; C10.1 v1(78.45,11.08) ; U20.8 v1(106.86,65.03) ; v1(62.81,94.18) 62.81,94.99 62.96,95.15 U5.59 ; U17.24 v1(84.13,87.27) ; U15.20 v1(70.85,25.29) ; U3.7 v1(28.16,59.01) ; U19.8 v1(82.87,107.76) ; v1(107.81,99.59) 107.81,100.43 108.14,100.75 U22.24 ; U11.2 v1(84.21,15.13) ; U23.24 v1(108.14,113.6) ; U5.38 v1(44.15,89.55) ; U22.8 v1(106.86,94.76) ; U18.24 v1(84.13,100.37) ; U1.7 v1(28.01,35.51) ; U4.42 v1(22.1,80.51) ; U20.24 v1(108.14,74.27) ; U3.42 v1(22.2,59.01) ; U19.24 v1(84.13,117.2) ; U6.20 v1(70.14,62.72) ; U21.8 v1(106.86,81.76) ; U11.9 v1(80.34,24.02) ; U5.80 v1(56.85,113.81) ; U18.8 v1(82.87,94.76) ; U23.8 v1(106.86,107.76) ; U5.17 v1(38.55,107.85) ; U1.31 v1(22.2,42.49)
  VCC1 w0.4: 38.37,50.67 U2.24 ; U2.24 39.2,51.5 ; U2.24 38.37,52.33 ; U2.24 37.54,51.5 ; 11.11,94.16 J1.62 ; J1.62 12.08,95.13 ; J1.62 12.08,93.19 ; J1.62 13.05,94.16 ; 101.5,29.07 L4.1 ; L4.1 101.5,30.93 ; L4.1 100.57,30 ; L4.1 102.43,30 ; 7,90.65 J1.29 ; J1.29 7,92.59 ; J1.29 7.97,91.62 ; J1.29 6.03,91.62 ; D1.A 98.27,60.93 ; D1.A 99.2,60 ; D1.A 98.27,59.07 ; D1.A 97.34,60 ; U7.8 21.37,98.38 ; U7.8 21.37,96.62 ; U7.8 20.49,97.5 ; U7.8 22.25,97.5 ; L6.1 102.43,10.08 ; L6.1 101.5,11.01 ; L6.1 101.5,9.15 ; L6.1 100.57,10.08 ; 20.49,100.04 U7.7 ; U7.7 21.37,99.16 ; U7.7 21.37,100.92 ; U7.7 22.25,100.04 ; D2.A 105.2,57.5 ; D2.A 103.34,57.5 ; D2.A 104.27,58.43 ; D2.A 104.27,56.57 ; 116.27,51.57 D4.A ; D4.A 116.27,53.43 ; D4.A 115.34,52.5 ; D4.A 117.2,52.5 ; 109.34,55 D3.A ; D3.A 110.27,54.07 ; D3.A 111.2,55 ; D3.A 110.27,55.93 ; J1.30 7,95.13 ; J1.30 7.97,94.16 ; J1.30 6.03,94.16 ; J1.30 7,93.19
  VCC2 w0.4: J1.29 7.97,91.62 ; J1.29 7,92.59 ; J1.29 6.03,91.62 ; J1.29 7,90.65 ; L6.1 101.5,11.01 ; L6.1 101.5,9.15 ; L6.1 100.57,10.08 ; L6.1 102.43,10.08 ; 110.27,54.07 D3.A ; D3.A 111.2,55 ; D3.A 109.34,55 ; D3.A 110.27,55.93 ; D1.A 98.27,60.93 ; D1.A 97.34,60 ; D1.A 99.2,60 ; D1.A 98.27,59.07 ; 20.49,100.04 U7.7 ; U7.7 21.37,99.16 ; U7.7 22.25,100.04 ; U7.7 21.37,100.92 ; 20.49,97.5 U7.8 ; U7.8 21.37,96.62 ; U7.8 21.37,98.38 ; U7.8 22.25,97.5 ; D2.A 105.2,57.5 ; D2.A 104.27,58.43 ; D2.A 104.27,56.57 ; D2.A 103.34,57.5 ; 11.11,94.16 J1.62 ; J1.62 12.08,95.13 ; J1.62 12.08,93.19 ; J1.62 13.05,94.16 ; J1.30 7,95.13 ; J1.30 6.03,94.16 ; J1.30 7,93.19 ; J1.30 7.97,94.16 ; 116.27,51.57 D4.A ; D4.A 116.27,53.43 ; D4.A 115.34,52.5 ; D4.A 117.2,52.5 ; U2.24 38.37,52.33 ; U2.24 37.54,51.5 ; U2.24 39.2,51.5 ; U2.24 38.37,50.67 ; L4.1 101.5,30.93 ; L4.1 102.43,30 ; L4.1 101.5,29.07 ; L4.1 100.57,30
  BOTTOM w0.4: C22.1 v1(104.53,71.5) ; C27.1 v1(104.53,110.5) ; v1(24.6,59.7) 24.7,59.8 24.7,60.82 C3.1 ; C26.1 v1(104.78,97.5) ; C21.1 v1(80.45,71.5) ; C28.1 v1(80.78,110.5) ; v1(104.78,84.7) 105.91,84.7 C24.1 ; C2.1 v1(38.5,48) ; C4.1 v1(25,80.95) ; C1.1 v1(25,36.14) ; C23.1 v1(80.45,84.5) ; C25.1 v1(80.45,97.5)
A0: length 15
  TOP w0.15: U4.36 18.22,84.32 v1(17.69,83.79)
  BOTTOM w0.15: J1.54 17.69,79.45 v1(17.69,83.79)
A1: length 13.9
  TOP w0.15: U4.35 v1(16.96,84.95)
  BOTTOM w0.15: J1.55 16.96,81.26 v1(16.96,84.95)
A2: length 13.2
  TOP w0.15: U4.33 v1(15.93,86.22)
  BOTTOM w0.15: J1.56 15.93,82.77 v1(15.93,86.22)
A3: length 11.7
  TOP w0.15: U4.32 17.19,86.86 v1(17.09,86.95)
  BOTTOM w0.15: v1(17.09,86.95) 15.56,86.95 14.29,85.69 14.29,83.67 J1.57
A4: length 9.9
  TOP w0.15: U4.30 16.21,88.13 J1.58
A5: length 9.1
  TOP w0.15: J1.59 14.3,88.76 U4.29
A6: length 8.6
  TOP w0.15: J1.60 13.03,90.03 U4.27
A7: length 8.6
  TOP w0.15: U4.26 13.03,90.67 J1.61
A8: length 15.3
  TOP w0.15: U3.47 18.76,55.83 15.22,52.29 8.31,52.29 J1.13
A9: length 14.5
  TOP w0.15: U3.46 15.71,56.47 14.07,54.83 8.31,54.83 J1.14
A10: length 13.9
  TOP w0.15: U3.44 14.18,57.74 13.54,57.1 8.04,57.1 J1.15
A11: length 14.1
  TOP w0.15: J1.16 8.1,57.5 12.9,57.5 13.77,58.37 U3.43
A12: length 13.9
  TOP w0.15: J1.17 8.12,60.02 12.97,60.02 13.08,59.91 16.86,59.91 17.13,59.64 U3.41
A13: length 17.3
  TOP w0.15: v1(13.53,60.82) 14.06,60.28 U3.40
  BOTTOM w0.15: J1.18 8.12,64.8 12.4,64.8 13.53,63.68 v1(13.53,60.82)
A14: length 15.2
  TOP w0.15: U3.38 v1(16.79,61.55)
  BOTTOM w0.15: v1(16.79,61.55) 13.24,65.1 8.12,65.1 J1.19
A15: length 16.9
  TOP w0.15: J1.20 9.51,66.25 9.51,64.74 11.84,62.41 18.78,62.41 19,62.18 U3.37
A16: length 8.9
  TOP w0.15: U1.47 13.75,32.33 J1.37
A17: length 8.3
  TOP w0.15: U1.46 12.31,32.97 J1.38
A18: length 77.7
  TOP w0.15: U1.44 12.48,34.24 12.08,34.64 J1.39
  BOTTOM w0.15: U2.6 43.58,61.78 43.58,55.88 40.4,52.7 18.69,52.7 15.55,49.56 8.19,49.56 8.04,49.71 6.83,49.71 5.69,48.56 5.69,38.07 6.7,37.05 10.77,37.05 J1.39
A19: length 58.3
  TOP w0.15: v1(13.83,34.98) 13.93,34.87 U1.43 21.41,34.87 21.68,34.6 24.11,34.6 24.29,34.77 v1(25,34.77)
  BOTTOM w0.15: v1(25,34.77) 25.71,34.77 25.79,34.7 34.1,34.7 47,47.6 47,56.84 44.83,59.01 44.83,60.48 U2.5 ; J1.40 13.83,36.53 v1(13.83,34.98)
A20: length 60.2
  TOP w0.15: U1.41 18.52,36.14 v1(18.09,35.71)
  BOTTOM w0.15: U2.4 47.4,57.72 47.4,45.79 34.48,32.87 20.93,32.87 v1(18.09,35.71) 17.19,35.71 J1.41
A21: length 50.3
  TOP w0.15: v1(17.29,36.88) 17.39,36.78 U1.40
  BOTTOM w0.15: v1(17.29,36.88) 17.29,43.06 16.99,43.36 ; 16.99,43.36 16.99,45.52 23.88,52.4 41.82,52.4 U2.3 ; 16.99,43.36 J1.42
A22: length 66.8
  TOP w0.15: U1.38 21.41,38.05 23.65,40.29 23.65,49.04 v1(22.92,49.77) 6.82,49.77 5.69,48.65 5.69,45.71 6.6,44.8 10.98,44.8 J1.43
  BOTTOM w0.15: U2.2 42.47,50.51 23.65,50.51 v1(22.92,49.77)
A23: length 47.2
  TOP w0.15: J1.44 v1(22.62,48.44) 23.35,47.71 23.35,40.59 21.45,38.68 U1.37
  BOTTOM w0.15: v1(22.62,48.44) 31.08,48.44 32.42,49.77 44.27,49.77 U2.1
AEN: length 50.8
  BOTTOM w0.15: U2.8 47.1,70.38 47.1,72.5 46.8,72.8 45.2,72.8 42.73,70.34 42.73,61.69 38.74,57.7 35.63,57.7 33.99,56.06 J1.47
BA0: length 106.4
  TOP w0.15: v1(35.7,39.4) 35.2,39.9 35.2,60.5 32.9,62.8 ; 31.21,75.29 31.21,77.11 31,77.33 U4.2 ; 31.21,75.29 29.9,73.98 29.9,72.72 30.8,71.82 31.22,71.82 32.9,70.14 32.9,62.8 ; 31.21,75.29 31.51,75 34.5,75 34.79,75.29 34.8,75.29 34.99,75.48 39.21,75.48 39.99,74.7 v1(43.7,74.7) ; v1(31.8,39.4) 31.09,39.4 31.01,39.32 U1.13 ; 32.9,62.8 30.91,62.8 30.89,62.82 U3.13 ; U5.6 v1(44.15,109.77)
  BOTTOM w0.15: v1(44.15,109.77) 43.1,108.72 43.1,78.1 43.7,77.5 v1(43.7,74.7) ; v1(35.7,39.4) v1(31.8,39.4)
BA1: length 125.4
  TOP w0.15: v1(32.01,63.55) 31.91,63.45 U3.14 ; U5.7 v1(42.88,113.81) ; v1(33.9,63.55) 34.71,63.55 35.14,63.12 38.23,63.12 39.4,61.95 39.4,38.9 31.75,31.25 28.73,31.25 27,32.98 27,38.48 28.47,39.95 U1.14 ; v1(42.88,76.03) 42.17,76.03 42.05,75.9 35.03,75.9 34.91,76.03 v1(34.2,76.03) 32.25,77.97 U4.3
  BOTTOM w0.15: v1(32.01,63.55) v1(33.9,63.55) 34.63,64.28 34.63,65.37 34.2,65.8 v1(34.2,76.03) ; v1(42.88,76.03) 42.88,76.73 42.7,76.92 42.7,112.92 42.88,113.1 v1(42.88,113.81)
BA2: length 133.1
  TOP w0.15: U5.8 v1(41.61,113.81) ; U4.5 34.7,79.24 35.75,78.19 v1(41.61,78.19) ; v1(33.77,64.72) 34.98,64.72 37.06,66.8 v1(37.06,67.62) 37.77,67.62 37.86,67.7 39.4,67.7 41.22,65.88 41.22,39.08 32.71,30.57 28.93,30.57 26.6,32.91 26.6,39.31 28.52,41.22 U1.16 ; U3.16 v1(31.71,64.72)
  BOTTOM w0.15: v1(37.06,67.62) 38.05,67.62 41.61,71.17 v1(41.61,78.19) v1(41.61,113.81) ; v1(31.71,64.72) v1(33.77,64.72)
BA3: length 91.2
  TOP w0.15: U3.17 v1(28.16,65.36) 27.4,64.6 27.4,51.21 28.45,50.17 29.08,50.17 32.38,46.87 32.38,43.24 31,41.86 U1.17 ; v1(33.4,80) 31.02,80 30.89,79.87 U4.6 ; U5.9 v1(40.34,109.95)
  BOTTOM w0.15: v1(40.34,109.95) 39.57,109.95 34.24,104.62 34.24,97.05 33.1,95.91 33.1,90.22 33.91,89.41 33.91,80.51 v1(33.4,80) 33.4,68.48 31.65,66.72 29.53,66.72 v1(28.16,65.36)
BA4: length 50.6
  TOP w0.15: U1.19 31.19,43.13 32.08,44.02 32.08,46.68 29.8,48.97 29.16,48.97 27.13,51 27.13,51.06 27.1,51.09 27.1,64.72 27.13,64.75 27.13,65.48 28.27,66.63 U3.19 30.91,66.63 31.06,66.77 31.65,66.77 32.44,67.57 32.44,70.13 31.65,70.92 31.23,70.92 29.5,72.65 29.5,74.17 29.71,74.38 v1(29.71,75.09) ; U4.8 v1(31.65,81.14)
  BOTTOM w0.15: v1(29.71,75.09) 29.71,79.2 v1(31.65,81.14)
BA5: length 48.4
  TOP w0.15: U4.9 28.32,81.78 27.4,80.86 27.4,70.89 27.51,70.78 v1(27.51,70.07) ; U1.20 27.44,43.76 25.4,45.8 25.4,64.88 25.43,64.91 25.43,65.52 25.4,65.56 25.4,66.56 24.9,67.06 v1(24.9,67.8) ; v1(27.51,67.76) 28,67.26 U3.20
  BOTTOM w0.15: v1(27.51,70.07) v1(27.51,67.76) 25.65,67.76 25.61,67.8 v1(24.9,67.8)
BA6: length 46
  TOP w0.15: v1(27.51,47) 26.6,47.91 26.6,68.36 26.77,68.53 ; 26.77,68.53 U3.22 ; 26.77,68.53 26.6,68.71 26.6,81.09 28.55,83.05 U4.11 ; v1(27.51,44.89) 27.65,45.03 U1.22
  BOTTOM w0.15: v1(27.51,47) v1(27.51,44.89)
BA7: length 49.2
  TOP w0.15: U1.23 27.78,45.67 25.75,47.7 v1(25.75,71.35) 25.75,80.92 28.52,83.68 U4.12 ; U3.23 28.84,69.17 28.54,69.47 v1(28.54,71.35)
  BOTTOM w0.15: v1(28.54,71.35) v1(25.75,71.35)
BD0: length 14.8
  TOP w0.15: U5.25 32.93,97.69 31.72,96.49 29.23,96.49 28.5,95.76 28.5,90.79 28.62,90.67 U4.23
BD1: length 18.2
  TOP w0.15: U5.24 28.59,98.96 28,98.37 28,90.63 28.59,90.03 U4.22
BD2: length 17.9
  TOP w0.15: U4.20 31.89,88.76 v1(32.08,88.95) ; U5.23 v1(32.08,100.23)
  BOTTOM w0.15: v1(32.08,88.95) v1(32.08,100.23)
BD3: length 20
  TOP w0.15: U4.19 v1(32.91,88.13) ; U5.22 v1(32.91,101.5)
  BOTTOM w0.15: v1(32.91,88.13) 32.91,89.99 32.8,90.09 32.8,96.04 32.91,96.14 v1(32.91,101.5)
BD4: length 22.5
  TOP w0.15: U4.17 v1(31.35,86.86) ; U5.21 v1(31.35,102.77)
  BOTTOM w0.15: v1(31.35,102.77) 31.35,102.06 31.2,101.91 31.2,87.72 31.35,87.57 v1(31.35,86.86)
BD5: length 27.7
  TOP w0.15: U5.20 30.54,104.04 30.1,103.6 28.2,103.6 27.4,102.8 27.4,87.19 28.22,86.37 28.45,86.37 28.59,86.22 U4.16
BD6: length 30.7
  TOP w0.15: U5.19 31.01,105.31 29.7,104 27.9,104 27.1,103.2 27.1,87.06 27.13,87.04 27.13,85.36 27.64,84.86 28.5,84.86 28.59,84.95 U4.14
BD7: length 33.1
  TOP w0.15: U4.13 27.67,84.32 26.53,85.46 26.53,104.04 29.07,106.58 U5.18
BD8: length 22.4
  TOP w0.15: U3.2 31.92,55.83 32.68,55.07 32.68,39.08 32.2,38.6 31.1,38.6 31.02,38.68 U1.12
BD9: length 23.7
  TOP w0.15: U3.3 30.91,56.47 31.06,56.32 31.96,56.32 32.98,55.31 32.98,38.83 32.35,38.19 31.06,38.19 30.91,38.05 U1.11
BD10: length 32.1
  TOP w0.15: U3.5 28.52,57.74 28.16,57.38 v1(28.16,51.54) ; U1.9 v1(27.81,36.78)
  BOTTOM w0.15: v1(28.16,51.54) 23.54,51.54 21.8,49.8 21.8,48.21 26.77,43.24 26.77,37.81 v1(27.81,36.78)
BD11: length 27.2
  TOP w0.15: U3.6 31.5,58.37 33.28,56.59 33.28,37.92 31.5,36.14 U1.8
BD12: length 29.4
  TOP w0.15: U3.8 31.04,59.64 33.58,57.1 33.58,37.41 31.04,34.87 U1.6
BD13: length 30.9
  TOP w0.15: U3.9 30.96,60.28 33.88,57.36 33.88,37.16 30.96,34.24 U1.5
BD14: length 33.7
  TOP w0.15: U1.3 31.01,32.97 34.18,36.14 34.18,58.37 31.01,61.55 U3.11
BD15: length 35.4
  TOP w0.15: U3.12 30.93,62.18 34.8,58.31 34.8,36.21 30.93,32.33 U1.2
BNC2: length 20.3
  TOP w0.15: C5.1 112.73,29.5 111.5,30.73 J2.1
  BOTTOM w0.15: L1.2 109,35 J2.1
BNC3: length 22.4
  TOP w0.15: L2.2 105.04,18.5 J3.1 ; C6.1 v1(111.5,10)
  BOTTOM w0.15: v1(111.5,10) J3.1
BRD: length 70.2
  TOP w0.15: v1(40.88,85.31) 40.88,91.69 45.95,96.77 45.95,114.27 46.05,114.36 46.05,116.85 46.46,117.26 54.59,117.26 54.95,116.91 54.95,114.61 56.62,112.93 U5.73
  BOTTOM w0.15: v1(40.88,85.31) 40.88,74.33 U2.16
BRESET: length 45.7
  TOP w0.15: v1(39.28,106.68) 39.28,109.15 37.41,111.03 35.13,111.03 34.66,111.5 34.66,113.58 35.27,114.2 U5.12
  BOTTOM w0.15: v1(39.28,106.68) 39.28,105.97 39.4,105.86 39.4,90.35 37.3,88.25 37.3,75.43 U2.15
BWR: length 52.9
  TOP w0.15: U5.54 61.71,88.8 61.4,88.49 v1(61.4,85.31) ; U2.17 39.64,70.55 65.31,70.55 67.4,72.64 67.4,73.54 62.55,78.39 v1(61.4,78.39)
  BOTTOM w0.15: v1(61.4,85.31) v1(61.4,78.39)
D0: length 59.8
  TOP w0.15: U4.37 22.51,83.68 23.53,82.67 23.53,70.03 v1(22.66,69.17) U3.26
  BOTTOM w0.15: v1(22.66,69.17) 21.34,69.17 19.67,67.49 6.79,67.49 4.9,69.38 4.9,86.98 J1.28
D1: length 34.8
  TOP w0.15: J1.27 10.66,82.88 18.84,82.88 19,83.05 U4.38 21.41,83.05 21.5,83.14 22.59,83.14 23.23,82.51 23.23,75.15 19.09,71.01 19.09,68.83 19.38,68.53 U3.27
D2: length 33.9
  TOP w0.15: U3.29 19.04,67.26 18.7,67.6 18.7,72.12 22.9,76.32 22.9,76.36 22.93,76.39 22.93,80.84 22.14,81.63 21.55,81.63 21.41,81.78 U4.40 16.44,81.78 15.64,82.58 8.42,82.58 J1.26
D3: length 39.4
  TOP w0.15: U3.30 19.02,66.63 17.5,68.15 v1(17.5,70.63) ; U4.41 15.24,81.14 14.29,80.19 8.27,80.19 J1.25
  BOTTOM w0.15: v1(17.5,70.63) 16.69,70.63 16.25,70.2 11.4,70.2 10.7,70.9 10.7,77.76 J1.25
D4: length 29.2
  TOP w0.15: 16.6,77.8 16.6,76.33 16.62,76.31 16.62,67.8 19.05,65.36 U3.32 ; 16.6,77.8 8.12,77.8 J1.24 ; 16.6,77.8 18.67,79.87 U4.43
D5: length 51.6
  TOP w0.15: J1.23 8.12,77.5 15,77.5 16.3,76.2 16.3,67.41 18.98,64.72 U3.33 ; U4.44 18.97,79.24 17,77.27 17,72.85 v1(17.78,72.08)
  BOTTOM w0.15: v1(17.78,72.08) 18.63,71.22 18.63,70.63 17.8,69.8 11.2,69.8 10,71 10,73.38 J1.23
D6: length 30.8
  TOP w0.15: U4.46 18.2,77.97 17.7,77.47 17.7,75.83 17.8,75.73 v1(17.8,75.02) ; J1.22 8.18,75.02 v1(15.4,75.02) 15.4,67.06 19.01,63.45 U3.35
  BOTTOM w0.15: v1(17.8,75.02) v1(15.4,75.02)
D7: length 58.1
  TOP w0.15: v1(18.53,77.19) 18.68,77.33 U4.47 ; U3.36 19,62.82 13.99,67.83 13.99,68.3 12.21,70.07 8.23,70.07 J1.21
  BOTTOM w0.15: v1(18.53,77.19) 18.53,86.67 17.4,87.81 6.74,87.81 5.6,86.67 5.6,72.7 J1.21
D8: length 20.3
  TOP w0.15: U1.36 17.23,39.32 14.96,37.05 11.86,37.05 10.71,35.91 10.71,31.83 J1.4
D9: length 19.4
  TOP w0.15: U1.35 15.52,39.95 14.97,39.4 11.74,39.4 10.11,37.77 10.11,33.77 J1.5
D10: length 17.7
  TOP w0.15: J1.6 9.51,35.71 9.51,37.69 11.53,39.7 13.29,39.7 14.81,41.22 U1.33
D11: length 16.7
  TOP w0.15: J1.7 8.61,37.35 8.61,38.91 11.56,41.86 U1.32
D12: length 15.3
  TOP w0.15: v1(14.1,42.6) 14.63,43.13 U1.30
  BOTTOM w0.15: v1(14.1,42.6) 13.29,42.6 12.82,42.13 10.85,42.13 J1.8
D13: length 14.5
  TOP w0.15: U1.29 14.21,43.76 12.69,42.24 8.42,42.24 J1.9
D14: length 13.9
  TOP w0.15: U1.27 13.42,45.03 12.79,44.4 8.04,44.4 J1.10
D15: length 14.4
  TOP w0.15: J1.11 8.27,47.17 15.21,47.17 16.71,45.67 U1.26
DATA: length 20.4
  TOP w0.15: U5.14 v1(38.55,111.66)
  BOTTOM w0.15: U7.1 29,98.5 30.1,99.61 30.1,103.21 v1(38.55,111.66)
DCLK: length 24.9
  TOP w0.15: U5.10 39.07,113.55 39.59,113.03 39.59,108.68 40.32,107.95 40.32,106.3 37.43,103.41 34.87,103.41 34.67,103.6 31.12,103.6 30.23,102.71 30.23,101.27 U7.2
DDIR: length 86.6
  TOP w0.15: U1.48 23.07,31.7 25.8,34.43 25.8,42.46 24.57,43.69 24.57,54.31 23.68,55.2 ; 20.25,91.3 21.48,91.3 23.83,88.96 23.83,60.05 23.38,59.6 v1(23.38,58.79) 23.38,55.5 23.68,55.2 ; 23.68,55.2 23.68,55.2 U3.48
  BOTTOM w0.15: v1(23.38,58.79) 24.87,58.79 27.74,61.66 U2.20
DEN: length 71.1
  TOP w0.15: U4.24 v1(33.94,91.3) ; 29.75,31.7 31.16,31.7 37.25,37.79 37.25,58 U2.21
  BOTTOM w0.15: U2.21 39.55,60.3 39.55,61.82 38.43,62.93 38.26,62.93 35.1,66.09 35.1,90.14 v1(33.94,91.3)
DHEN: length 9.3
  TOP w0.15: 29.75,55.2 31.5,55.2 v1(31.65,55.05)
  BOTTOM w0.15: U2.22 36.84,55.05 v1(31.65,55.05)
FPGA: length 30
  TOP w0.15: U5.30 v1(38.55,91.34)
  BOTTOM w0.15: U2.18 36.84,66.74 35.82,67.76 35.82,88.61 v1(38.55,91.34)
GAIN: length 120.3
  TOP w0.15: U10.6 86.71,44.13 87.32,44.74 87.32,45.8 86.92,46.2 76.56,46.2 76.5,46.14 ; U5.28 38.38,93.88 39.66,92.61 39.66,85.48 43.97,81.17 60.94,81.17 68.43,73.67 68.43,52.66 72.49,48.6 74.04,48.6 76.5,46.14 ; 76.5,46.14 76.5,31.56 81.18,26.88 86.35,26.88 87.23,25.99 87.23,25.01 86.44,24.21 U13.6
HS: length 33.1
  TOP w0.15: U5.29 v1(38.55,92.61)
  BOTTOM w0.15: U2.19 35.52,67.05 35.52,89.58 v1(38.55,92.61)
LED1: length 31.3
  TOP w0.15: D1.C 89.06,60 89.06,60.9 88.79,60.9 88.79,60 88.51,60 88.51,60.9 88.23,60.9 88.23,60 87.96,60 87.96,60.9 87.68,60.9 87.68,60 87.4,60 87.4,60.9 87.12,60.9 87.12,60 86.85,60 86.85,60.9 86.57,60.9 86.57,60 86.29,60 86.29,60.9 86.02,60.9 86.02,60 85.74,60 85.74,60.9 85.46,60.9 85.46,60 85.19,60 85.19,60.9 84.91,60.9 84.91,60 84.63,60 84.63,60.9 84.35,60.9 84.35,60 84.08,60 84.08,60.9 83.8,60.9 83.8,60 R1.2
LED2: length 31.3
  TOP w0.15: R2.2 83.71,57.5 83.71,58.5 83.99,58.5 83.99,57.5 84.27,57.5 84.27,58.5 84.54,58.5 84.54,57.5 84.82,57.5 84.82,58.5 85.1,58.5 85.1,57.5 85.38,57.5 85.38,58.5 85.65,58.5 85.65,57.5 85.93,57.5 85.93,58.5 86.21,58.5 86.21,57.5 86.48,57.5 86.48,58.5 86.76,58.5 86.76,57.5 D2.C
LED3: length 31.3
  TOP w0.15: R3.2 83.74,55 83.74,56 84.02,56 84.02,55 84.3,55 84.3,56 84.57,56 84.57,55 84.85,55 84.85,56 85.13,56 85.13,55 D3.C
LED4: length 31.3
  TOP w0.15: R4.2 D4.C
MCLK: length 50
  TOP w0.15: v1(31.35,83.58) 36.18,83.58 38.44,85.84 38.44,89.47 37.84,90.07 U5.31
  BOTTOM w0.15: J1.52 18.07,68.76 21.41,72.1 31.48,72.1 32,72.62 32,73.6 31.4,74.2 29.4,74.2 28.9,74.7 28.9,81.13 v1(31.35,83.58)
MEMORY.RA0: length 184.5
  TOP w0.15: 81.06,78.59 79.85,78.59 79.06,79.39 U17.5 ; 81.06,78.59 80.96,78.69 80.96,80.96 81.6,81.6 81.6,85.49 79.69,87.4 79.69,90.3 79.58,90.41 79.58,91.59 79.69,91.7 79.69,93.86 79.58,93.97 79.58,92.92 ; 81.06,78.59 81.06,77.38 80.96,77.28 80.96,75.21 v1(79.06,73.31) ; 103.36,69.89 102.55,70.7 79.83,70.7 79.77,70.77 v1(79.06,70.77) U16.5 ; 103.36,69.89 v1(111.25,69.89) ; 103.36,69.89 103.06,69.59 U20.5 ; v1(67.43,117.57) 67.43,114.06 66.93,113.56 63.65,113.56 62.56,114.65 62.56,116.95 62.18,117.34 58.12,117.34 U5.79 ; U23.5 103.06,104.52 103.86,103.7 108.23,103.7 108.77,103.17 108.77,97.75 110.04,96.48 110.04,91.7 109.92,91.59 109.92,91.68 ; 79.58,92.92 79.2,92.92 U18.5 ; 79.58,92.92 79.58,101.03 79.69,101.14 79.69,103.3 79.4,103.58 79.4,104.27 79.06,104.62 U19.5 79.06,107.5 77.72,108.83 77.72,112.16 77.03,112.84 77.03,114.03 77.15,114.14 77.15,116.3 77.2,116.34 v1(77.2,117.2) ; U21.5 103.06,81.05 105.1,83.09 107.22,83.09 110.14,86.01 v1(110.14,87.23) 110.14,88.06 110.04,88.16 110.04,90.28 110.14,90.38 110.14,91.68 109.92,91.68 ; 109.92,91.68 109.92,91.59 103.86,91.59 103.06,92.39 U22.5
  BOTTOM w0.15: v1(77.2,117.2) 68.51,117.2 68.14,117.57 v1(67.43,117.57) ; v1(110.14,87.23) 111.55,85.82 111.55,80.09 110.91,79.45 110.91,73.3 111.25,72.96 v1(111.25,69.89) ; v1(79.06,73.31) v1(79.06,70.77)
MEMORY.RA1: length 205.5
  TOP w0.15: U18.4 77.78,94.05 77.5,94.33 77.5,97.45 78.6,98.55 78.6,100.98 78.42,101.16 78.42,103.44 77.78,104.07 77.78,104.59 ; v1(74.5,109.43) 74.5,106.97 74.61,106.86 74.61,104.73 74.75,104.59 77.78,104.59 ; U5.78 v1(59.39,113.81) ; U17.4 77.78,78.27 78.42,77.63 78.42,75.14 78.31,75.03 78.31,72.53 ; v1(53.28,108.27) 53.28,102.67 62.7,93.25 65.95,93.25 66.3,92.9 66.3,88.18 70.24,84.24 70.24,72.36 71.8,70.8 72.6,70 72.6,68.9 72.1,68.4 72.1,65.5 72.4,65.2 77.4,65.2 77.78,65.59 U16.4 77.78,72.01 78.31,72.53 ; 77.78,104.59 U19.4 ; U23.4 101.68,105.88 v1(101.68,107.4) ; v1(101.77,81.4) 101.78,81.38 U21.4 ; 78.31,72.53 80.77,72.53 81.59,71.71 v1(102,71.71) ; v1(101.9,69.6) 101.9,68.89 101.78,68.78 U20.4 ; U22.4 v1(101.78,95.19)
  BOTTOM w0.15: 70.97,109.43 v1(74.5,109.43) ; 70.97,109.43 70.7,109.7 68.9,109.7 68.6,109.4 63.02,109.4 59.39,113.03 v1(59.39,113.81) ; 70.97,109.43 70.97,108.47 70.5,108 68.69,108 68.29,108.4 54.12,108.4 53.99,108.27 v1(53.28,108.27) ; v1(101.68,107.4) 101.68,106.69 101.6,106.61 101.6,96.08 101.78,95.9 v1(101.78,95.19) 101.78,94.48 101.5,94.19 101.5,82.38 101.77,82.11 v1(101.77,81.4) 101.77,80.58 101.1,79.92 101.1,73.42 102,72.52 v1(102,71.71) 102,71 101.9,70.89 v1(101.9,69.6)
MEMORY.RA2: length 194.3
  TOP w0.15: U5.77 v1(60.66,113.81) ; U17.3 76.52,78.63 v1(77.01,78.14) ; 73.02,71.32 70.84,73.51 70.84,84.46 69.8,85.5 69.8,88.4 70.2,88.8 v1(70.2,97.29) 70.2,108.46 v1(69.79,108.87) ; 73.02,71.32 73.02,69.5 ; 73.02,71.32 73.32,71.62 v1(77.01,71.62) ; U20.3 100.52,69.1 v1(100.3,69.31) 99.59,69.31 99.41,69.5 v1(94.7,69.5) ; v1(75.9,97.29) 76.6,96.59 76.6,94.03 76.52,93.94 U18.3 ; v1(100.3,94.4) 100.3,92.99 U22.3 ; U16.3 76.52,68.08 75.09,69.5 73.02,69.5 ; 73.02,69.5 v1(73.02,66) ; v1(74.19,111.9) 76.52,109.57 U19.3 ; U23.3 v1(100.52,107.76) ; U21.3 v1(100.52,82.56)
  BOTTOM w0.15: v1(77.01,71.62) 77.01,72.33 77.3,72.62 77.3,77.14 77.01,77.43 v1(77.01,78.14) ; v1(69.79,108.87) 62.8,108.87 58.36,113.31 58.36,114.03 58.87,114.54 59.93,114.54 v1(60.66,113.81) 62.57,111.9 v1(74.19,111.9) ; v1(100.3,69.31) 100.3,70.37 100.3,70.37 100.3,78.92 98.5,80.72 98.5,82.16 98.91,82.56 v1(100.52,82.56) 100.52,94.19 v1(100.3,94.4) 101.03,95.13 101.03,103.77 100.52,104.29 v1(100.52,107.76) ; v1(73.02,66) 93.7,66 94.7,67 v1(94.7,69.5) ; v1(75.9,97.29) v1(70.2,97.29)
MEMORY.RA3: length 152.5
  TOP w0.15: v1(92.49,68.49) v1(99.25,68.49) U20.2 ; v1(75.25,81.4) U17.2 ; U19.2 v1(75.25,108.27) 75.25,110.07 74.85,110.47 74.34,110.47 73.75,109.88 73.75,108.02 73.45,107.72 73.45,104.64 74.09,104 75.13,104 75.88,103.25 75.88,100.3 74.9,99.32 74.9,94.39 75.25,94.05 U18.2 75.25,91.52 74.57,90.84 v1(73.75,90.84) ; 98.5,93.22 98.61,93.1 98.61,91.7 98.5,91.59 98.5,90.8 98.89,90.41 100.91,90.41 101.15,90.16 101.15,85.58 99.25,83.68 v1(99.25,81.76) U21.2 ; 98.5,93.22 98.81,93.22 U22.2 ; 98.5,93.22 98.5,95.22 v1(98.28,95.43) ; U5.76 v1(61.93,113.74) ; v1(74.19,68.49) 75,68.49 75.25,68.25 U16.2 ; v1(98.28,100.37) 98.61,100.7 98.61,103.67 99.25,104.31 U23.2
  BOTTOM w0.15: v1(75.25,108.27) 75.25,111.91 74.23,112.93 62.74,112.93 v1(61.93,113.74) ; v1(98.28,95.43) v1(98.28,100.37) ; v1(99.25,68.49) 100.53,68.49 101.1,69.06 101.1,70 100.6,70.5 100.6,80.4 v1(99.25,81.76) ; v1(92.49,68.49) 91.67,68.49 91.08,67.9 79.1,67.9 78.51,68.49 v1(74.19,68.49) 74.19,81.4 ; 74.19,81.4 v1(75.25,81.4) ; 74.19,81.4 72.88,81.4 71.99,82.29 71.99,90.3 72.53,90.84 v1(73.75,90.84)
MEMORY.RA4: length 279.1
  TOP w0.15: v1(97.24,91.08) 97.24,89.35 97.38,89.22 U21.32 ; 72.72,100.7 73.72,100.7 73.97,100.95 U18.32 ; 72.72,100.7 v1(72.72,110.39) 72.72,112.58 73.97,113.83 U19.32 ; 72.72,100.7 72.52,100.5 72.52,89.72 v1(73.02,89.22) U17.32 ; v1(74.51,82.8) 74.51,82.09 74.4,81.98 74.4,81.05 74.61,80.84 74.61,78.53 75.88,77.26 75.88,75.28 75.64,75.03 74.78,75.03 73.97,75.83 U16.32 ; v1(55.04,110.39) 55.75,110.39 55.94,110.2 63.07,110.2 63.26,110.39 U5.71 v1(67.05,110.39) ; v1(42.72,118.2) 43.32,118.8 111.43,118.8 113.85,116.38 113.85,114.14 113.73,114.03 113.73,110.1 114.37,109.46 116.04,109.46 118.58,106.92 118.58,88.5 116.47,86.4 115.87,86.4 115.12,87.15 115.12,90.16 114.88,90.41 111.45,90.41 111.19,90.15 111.19,84.38 109.61,82.79 105.86,82.79 104.84,81.77 104.84,80.97 104.96,80.86 104.96,78.75 104.21,78 98.48,78 97.97,77.5 U20.32 ; U22.32 v1(97.02,102.22) v1(97.02,105.03) ; U23.32 97.21,115.22 97.02,115.03 v1(97.02,114.22)
  BOTTOM w0.15: v1(72.72,110.39) 72.01,110.39 71.92,110.3 67.85,110.3 67.76,110.39 v1(67.05,110.39) ; v1(73.02,89.22) 77.18,89.22 77.5,88.9 ; 77.5,88.9 95.95,88.9 97.24,90.19 v1(97.24,91.08) 97.24,91.79 97.33,91.88 97.33,101.2 97.02,101.51 v1(97.02,102.22) ; 77.5,88.9 77.5,87.2 77.1,86.8 75.76,86.8 74.51,85.55 v1(74.51,82.8) ; v1(55.04,110.39) 48.14,110.39 45.22,113.31 45.22,114.19 42.72,116.68 v1(42.72,118.2) ; v1(97.02,114.22) 97.02,113.42 96.7,113.1 96.7,106.77 97.02,106.45 v1(97.02,105.03)
MEMORY.RA5: length 181.5
  TOP w0.15: v1(97.35,86.41) 99.25,88.31 U21.31 ; v1(95.86,113.43) 98.74,113.43 99.25,113.93 U23.31 ; 72.51,84.93 72.2,84.62 72.2,78.11 72.91,77.41 74.44,77.41 75.25,76.61 U16.31 ; 72.51,84.93 72.51,87.73 ; 72.51,84.93 v1(77.85,84.93) ; U18.31 75.25,102.89 74.42,103.7 73.92,103.7 73.16,104.47 73.16,109.7 73.7,110.25 73.7,110.9 73.5,111.1 73.45,111.1 73.1,111.45 73.1,112.4 73.63,112.93 73.67,112.93 74.61,113.86 74.61,116.3 74.5,116.41 74.5,115.66 ; 72.51,87.73 71.39,88.86 v1(71.39,111.12) 71.89,111.63 71.89,114.75 73.55,116.41 74.4,116.41 74.5,116.31 74.5,115.66 ; 72.51,87.73 75.03,87.73 75.25,87.95 U17.31 ; 74.5,115.66 74.5,115.37 74.65,115.22 U19.31 ; U5.70 67.72,109.12 67.9,109.3 67.9,111 67.7,111.2 66.02,111.2 65.95,111.12 63.55,111.12 v1(62.81,111.12) ; v1(95.86,105.03) 95.86,99.5 ; 95.86,99.5 98.47,99.5 99.25,100.27 U22.31 ; 95.86,99.5 94.8,98.44 94.8,84.22 95.94,83.08 v1(95.94,80.11) ; U20.31 v1(99.25,74.6)
  BOTTOM w0.15: v1(95.86,105.03) v1(95.86,113.43) ; 98.08,80.41 97.78,80.11 v1(95.94,80.11) ; 98.08,80.41 98.08,85.68 v1(97.35,86.41) 91.25,86.41 90.36,87.3 86.6,87.3 85.7,86.4 83.6,86.4 83.3,86.7 83.3,87.9 82.9,88.3 78.74,88.3 77.85,87.41 v1(77.85,84.93) ; 98.08,80.41 99.25,79.24 v1(99.25,74.6) ; v1(62.81,111.12) 63.52,111.12 63.59,111.2 70.6,111.2 70.68,111.12 v1(71.39,111.12)
MEMORY.RA6: length 170.3
  TOP w0.15: U21.30 100.52,87.95 98.16,85.6 96.21,85.6 ; v1(67.16,107.53) 66.84,107.85 U5.69 62.67,107.85 59.88,105.06 v1(59.88,104.04) ; U19.30 76.52,113.7 v1(76.05,113.23) ; 96.21,85.6 95.5,84.89 95.5,84.2 96.8,82.9 96.8,77.92 96.1,77.22 96.1,74.77 97.07,73.8 99.7,73.8 100.52,74.61 U20.30 ; 96.21,85.6 v1(96.21,90.25) 95.1,91.36 95.1,97.7 95.7,98.3 97.92,98.3 v1(100.22,100.6) 100.22,101.92 U22.30 ; v1(73.24,74.6) 76.16,74.6 76.52,74.95 U16.30 ; U17.30 76.52,87.69 v1(76.6,87.6) 77.15,88.15 77.15,97.76 76.52,98.39 U18.30 v1(76.52,103.84) ; U23.30 v1(100.52,113.41) ; v1(73.24,83.7) v1(73.24,78.16)
  BOTTOM w0.15: v1(67.16,107.53) 67.87,107.53 68.1,107.3 75.6,107.3 76.05,107.75 v1(76.05,113.23) ; v1(73.24,78.16) v1(73.24,74.6) ; v1(59.88,104.04) 60.59,104.04 60.65,104.1 75.54,104.1 75.81,103.84 v1(76.52,103.84) ; v1(100.52,113.41) 100.52,109.11 99.7,108.3 99.7,101.93 100.22,101.41 v1(100.22,100.6) ; v1(96.21,90.25) 95.4,90.25 95.14,90 72.6,90 72.29,89.69 72.29,88.55 73.24,87.6 ; 73.24,87.6 v1(73.24,83.7) ; 73.24,87.6 v1(76.6,87.6)
MEMORY.RA7: length 298
  TOP w0.15: v1(83.27,69.27) 82.64,69.9 81.67,69.9 81.2,69.43 81.2,68.09 80.96,67.85 80.96,65.48 82.74,63.7 108.47,63.7 v1(109.6,64.83) ; U23.29 101.78,113.62 100.77,112.6 v1(94.75,112.6) ; U22.29 101.78,103.99 102.41,104.62 102.41,106.91 102.6,107.1 102.6,108 102,108.6 95.51,108.6 v1(94.95,108.04) 94.95,107.33 94.5,106.88 94.5,83.8 95.5,82.8 95.5,81.33 95.1,80.93 95.1,75.33 97.03,73.4 100.13,73.4 101.78,75.06 U20.29 ; 61.9,102.4 61.9,100.05 63.62,98.33 66.21,98.33 69.6,94.94 69.6,89.1 68.9,88.4 v1(68.9,87) ; 61.9,102.4 61.1,102.4 60.8,102.7 60.8,104 62.11,105.31 U5.67 65.72,105.31 66.22,105.81 v1(67.89,105.81) ; 61.9,102.4 62.07,102.57 v1(62.81,102.57) ; v1(70.9,87) 70.9,86 71.44,85.46 71.44,75.27 72.9,73.8 73.63,73.8 74.02,74.19 77.02,74.19 77.78,74.95 U16.29 77.78,76.89 77.37,77.3 77.01,77.3 76.9,77.41 76.7,77.41 75.88,78.22 75.88,80.79 76.79,81.7 v1(78.84,81.7) 78.84,85.41 77.7,86.54 77.7,87.95 77.78,88.04 U17.29 ; U19.29 v1(77.78,113.48) ; U18.29 v1(77.78,100.6) ; v1(108.9,86.5) 108.9,88.02 108.77,88.15 108.77,90.26 108.63,90.41 105.2,90.41 104.96,90.16 104.96,88.14 105.2,87.91 105.2,86.17 104.63,85.6 102.6,85.6 101.78,86.42 U21.29
  BOTTOM w0.15: v1(94.95,108.04) 94.95,112.39 v1(94.75,112.6) 92.25,115.1 79.4,115.1 v1(77.78,113.48) 77.78,107.48 76.11,105.81 v1(67.89,105.81) ; v1(77.78,100.6) 74.79,103.6 63.83,103.6 v1(62.81,102.57) ; v1(83.27,69.27) 82.34,70.2 79.7,70.2 79.4,69.9 78.82,69.9 78.1,70.62 78.1,77.58 81.2,80.68 81.2,81.8 80.8,82.2 79.34,82.2 v1(78.84,81.7) ; v1(108.9,86.5) 109.4,86 110.52,86 111.25,85.27 111.25,81.29 110.61,80.65 110.61,72.7 110.95,72.36 110.95,71.01 109.6,69.66 v1(109.6,64.83) ; v1(70.9,87) v1(68.9,87)
